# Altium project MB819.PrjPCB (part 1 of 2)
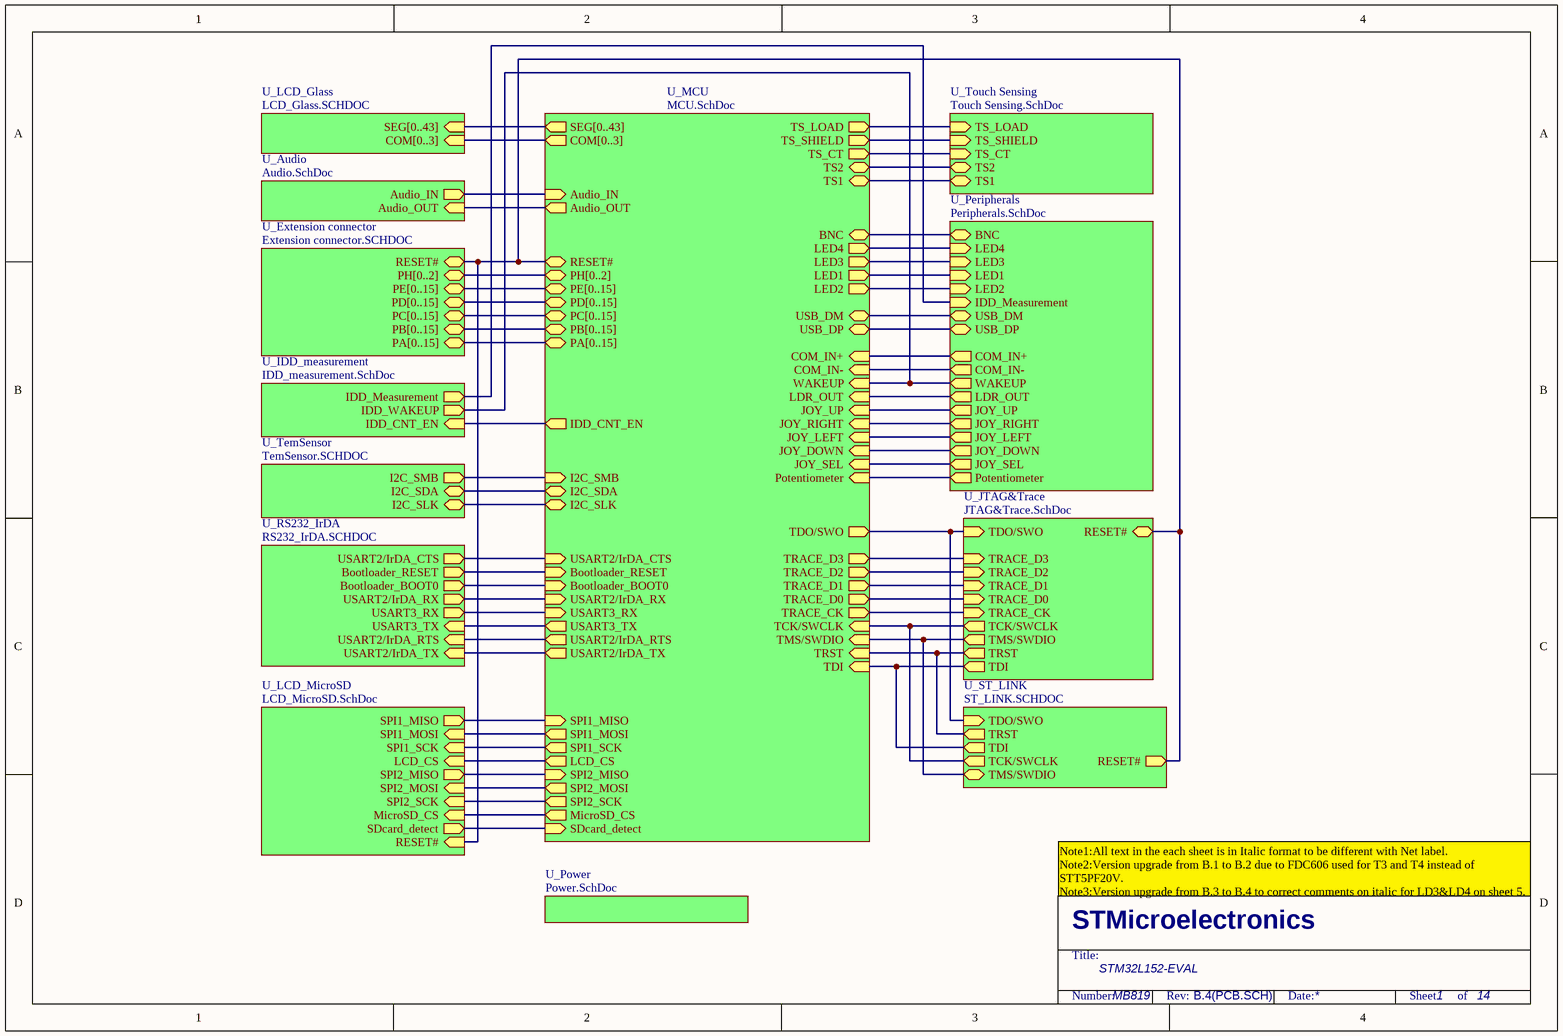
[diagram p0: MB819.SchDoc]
14 sheets, 334 parts. Net scope: hierarchical (ports join the sheet entries above them; power ports are global).
Board file: MB819.PCBDOC
Sheets:
  MB819.SchDoc
    U_Audio = Audio.SchDoc
    U_Extension connector = Extension connector.SCHDOC
    U_JTAG&Trace = JTAG&Trace.SchDoc
    U_LCD_Glass = LCD_Glass.SCHDOC
    U_LCD_MicroSD = LCD_MicroSD.SchDoc
    U_MCU = MCU.SchDoc
    U_Peripherals = Peripherals.SchDoc
    U_Power = Power.SchDoc
    U_RS232_IrDA = RS232_IrDA.SCHDOC
    U_ST_LINK = ST_LINK.SCHDOC
    U_TemSensor = TemSensor.SCHDOC
    U_Touch Sensing = Touch Sensing.SchDoc
    U_IDD_measurement = IDD_measurement.SchDoc

## Sheet MB819.SchDoc
size A4; Revision: B.4(PCB.SCH)

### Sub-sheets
U_Audio = Audio.SchDoc: Audio_OUT (in), Audio_IN (out)
U_Extension connector = Extension connector.SCHDOC: PA[0..15] (bidir), PB[0..15] (bidir), PC[0..15] (bidir), PD[0..15] (bidir), PE[0..15] (bidir), RESET# (bidir), PH[0..2] (bidir)
U_IDD_measurement = IDD_measurement.SchDoc: IDD_Measurement (out), IDD_CNT_EN (in), IDD_WAKEUP (out)
U_JTAG&Trace = JTAG&Trace.SchDoc: TDI (out), TRST (out), TMS/SWDIO (out), TCK/SWCLK (out), TDO/SWO (in), TRACE_D3 (in), TRACE_D2 (in), TRACE_D1 (in), TRACE_D0 (in), TRACE_CK (in), RESET# (bidir)
U_LCD_Glass = LCD_Glass.SCHDOC: SEG[0..43] (in), COM[0..3] (in)
U_LCD_MicroSD = LCD_MicroSD.SchDoc: MicroSD_CS (in), SPI1_SCK (in), SPI1_MOSI (in), LCD_CS (in), SPI1_MISO (out), SDcard_detect (out), RESET# (in), SPI2_SCK (in), SPI2_MOSI (in), SPI2_MISO (out)
U_MCU = MCU.SchDoc: PA[0..15] (bidir), PB[0..15] (bidir), PC[0..15] (bidir), PD[0..15] (bidir), PE[0..15] (bidir), RESET# (bidir), Bootloader_BOOT0 (in), Bootloader_RESET (in), PH[0..2] (bidir), TRACE_D3 (out), TRACE_D2 (out), TRACE_D1 (out), TRACE_D0 (out), TRACE_CK (out), SEG[0..43] (out), WAKEUP (in), Audio_OUT (out), BNC (bidir), TS_LOAD (out), SDcard_detect (in), JOY_SEL (in), JOY_DOWN (in), JOY_LEFT (in), JOY_RIGHT (in), JOY_UP (in), MicroSD_CS (out), SPI1_SCK (out), SPI1_MOSI (out), LCD_CS (out), SPI1_MISO (in), SPI2_SCK (out), SPI2_MOSI (out), SPI2_MISO (in), Potentiometer (in), Audio_IN (in), IDD_CNT_EN (out), TS1 (bidir), TS2 (bidir), TS_SHIELD (out), TS_CT (out), COM[0..3] (out), USB_DM (bidir), USB_DP (bidir), TDI (in), TRST (in), TMS/SWDIO (in), TCK/SWCLK (in), TDO/SWO (out), USART3_TX (out), USART3_RX (in), LED4 (out), LED3 (out), LED1 (out), LED2 (out), USART2/IrDA_TX (out), USART2/IrDA_CTS (in), USART2/IrDA_RX (in), USART2/IrDA_RTS (out), LDR_OUT (in), COM_IN- (in), COM_IN+ (in), I2C_SLK (bidir), I2C_SDA (bidir), I2C_SMB (in)
U_Peripherals = Peripherals.SchDoc: BNC (bidir), Potentiometer (out), LED4 (in), LED3 (in), LED1 (in), LED2 (in), JOY_SEL (out), JOY_DOWN (out), JOY_LEFT (out), JOY_RIGHT (out), JOY_UP (out), LDR_OUT (out), USB_DM (bidir), USB_DP (bidir), WAKEUP (out), COM_IN- (out), COM_IN+ (out), IDD_Measurement (in)
U_Power = Power.SchDoc: no entries
U_RS232_IrDA = RS232_IrDA.SCHDOC: USART2/IrDA_TX (in), USART2/IrDA_CTS (out), Bootloader_RESET (out), Bootloader_BOOT0 (out), USART2/IrDA_RX (out), USART2/IrDA_RTS (in), USART3_TX (in), USART3_RX (out)
U_ST_LINK = ST_LINK.SCHDOC: TMS/SWDIO (bidir), TCK/SWCLK (out), TDO/SWO (in), TDI (out), TRST (out), RESET# (out)
U_TemSensor = TemSensor.SCHDOC: I2C_SLK (bidir), I2C_SDA (bidir), I2C_SMB (out)
U_Touch Sensing = Touch Sensing.SchDoc: TS_LOAD (in), TS1 (bidir), TS2 (bidir), TS_SHIELD (in), TS_CT (in)

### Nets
PC8: sheet U_MCU/TS_SHIELD, sheet U_Touch Sensing/TS_SHIELD
PA0: sheet U_MCU/WAKEUP, sheet U_Peripherals/WAKEUP, sheet U_IDD_measurement/IDD_WAKEUP
PA4: sheet U_Audio/Audio_OUT, sheet U_MCU/Audio_OUT
PA5: sheet U_MCU/BNC, sheet U_Peripherals/BNC
PA11: sheet U_MCU/USB_DM, sheet U_Peripherals/USB_DM
PA12: sheet U_MCU/USB_DP, sheet U_Peripherals/USB_DP
PA13: sheet U_JTAG&Trace/TMS/SWDIO, sheet U_MCU/TMS/SWDIO, sheet U_ST_LINK/TMS/SWDIO
PA14: sheet U_JTAG&Trace/TCK/SWCLK, sheet U_MCU/TCK/SWCLK, sheet U_ST_LINK/TCK/SWCLK
PA15: sheet U_JTAG&Trace/TDI, sheet U_MCU/TDI, sheet U_ST_LINK/TDI
PB2: sheet U_MCU/TS_LOAD, sheet U_Touch Sensing/TS_LOAD
PB3: sheet U_JTAG&Trace/TDO/SWO, sheet U_MCU/TDO/SWO, sheet U_MCU/COM_IN-, sheet U_Peripherals/COM_IN-, sheet U_ST_LINK/TDO/SWO
PB5: sheet U_MCU/COM_IN+, sheet U_Peripherals/COM_IN+
PB6: sheet U_MCU/I2C_SLK, sheet U_TemSensor/I2C_SLK
PB7: sheet U_MCU/I2C_SDA, sheet U_TemSensor/I2C_SDA
PB12: sheet U_MCU/Potentiometer, sheet U_Peripherals/Potentiometer
PB13: sheet U_LCD_MicroSD/SPI2_SCK, sheet U_MCU/SPI2_SCK
PB14: sheet U_LCD_MicroSD/SPI2_MISO, sheet U_MCU/SPI2_MISO
PB15: sheet U_LCD_MicroSD/SPI2_MOSI, sheet U_MCU/SPI2_MOSI
PC6: sheet U_MCU/TS1, sheet U_Touch Sensing/TS1
PC7: sheet U_MCU/TS2, sheet U_Touch Sensing/TS2
PC9: sheet U_MCU/TS_CT, sheet U_Touch Sensing/TS_CT
PC13: sheet U_MCU/IDD_CNT_EN, sheet U_IDD_measurement/IDD_CNT_EN
PD0: sheet U_MCU/LED1, sheet U_Peripherals/LED1
PD1: sheet U_MCU/LED2, sheet U_Peripherals/LED2
PD3: sheet U_MCU/USART2/IrDA_CTS, sheet U_RS232_IrDA/USART2/IrDA_CTS
PD4: sheet U_MCU/USART2/IrDA_RTS, sheet U_RS232_IrDA/USART2/IrDA_RTS
PD5: sheet U_MCU/USART2/IrDA_TX, sheet U_RS232_IrDA/USART2/IrDA_TX
PD6: sheet U_MCU/USART2/IrDA_RX, sheet U_RS232_IrDA/USART2/IrDA_RX
PD7: sheet U_LCD_MicroSD/MicroSD_CS, sheet U_MCU/MicroSD_CS
PE2: sheet U_JTAG&Trace/TRACE_CK, sheet U_MCU/TRACE_CK
PE3: sheet U_JTAG&Trace/TRACE_D0, sheet U_MCU/TRACE_D0
PE4: sheet U_JTAG&Trace/TRACE_D1, sheet U_MCU/TRACE_D1
PE5: sheet U_JTAG&Trace/TRACE_D2, sheet U_MCU/TRACE_D2
PE6: sheet U_JTAG&Trace/TRACE_D3, sheet U_MCU/TRACE_D3
PE7: sheet U_Audio/Audio_IN, sheet U_MCU/Audio_IN
PE8: sheet U_MCU/JOY_SEL, sheet U_Peripherals/JOY_SEL
PE9: sheet U_MCU/JOY_UP, sheet U_Peripherals/JOY_UP
PE10: sheet U_MCU/JOY_DOWN, sheet U_Peripherals/JOY_DOWN
PE11: sheet U_MCU/JOY_RIGHT, sheet U_Peripherals/JOY_RIGHT
PE12: sheet U_MCU/JOY_LEFT, sheet U_Peripherals/JOY_LEFT
PE13: sheet U_LCD_MicroSD/SPI1_SCK, sheet U_MCU/SPI1_SCK
PE14: sheet U_LCD_MicroSD/SPI1_MISO, sheet U_MCU/SPI1_MISO
PE15: sheet U_LCD_MicroSD/SPI1_MOSI, sheet U_MCU/SPI1_MOSI
PH2: sheet U_LCD_MicroSD/LCD_CS, sheet U_MCU/LCD_CS
RESET#: sheet U_Extension connector/RESET#, sheet U_JTAG&Trace/RESET#, sheet U_LCD_MicroSD/RESET#, sheet U_MCU/RESET#, sheet U_ST_LINK/RESET#
T_JRST: sheet U_JTAG&Trace/TRST, sheet U_MCU/TRST, sheet U_ST_LINK/TRST
NetC25_1: sheet U_Peripherals/IDD_Measurement, sheet U_IDD_measurement/IDD_Measurement
NetCN4_10: sheet U_LCD_MicroSD/SDcard_detect, sheet U_MCU/SDcard_detect
NetD2_2: sheet U_MCU/Bootloader_RESET, sheet U_RS232_IrDA/Bootloader_RESET
NetJP7_3: sheet U_MCU/USART3_TX, sheet U_RS232_IrDA/USART3_TX
NetJP8_3: sheet U_MCU/USART3_RX, sheet U_RS232_IrDA/USART3_RX
NetJP10_1: sheet U_MCU/LDR_OUT, sheet U_Peripherals/LDR_OUT
NetJP11_2: sheet U_MCU/I2C_SMB, sheet U_TemSensor/I2C_SMB
NetJP18_1: sheet U_MCU/LED3, sheet U_Peripherals/LED3
NetJP19_1: sheet U_MCU/LED4, sheet U_Peripherals/LED4
NetR138_2: sheet U_MCU/Bootloader_BOOT0, sheet U_RS232_IrDA/Bootloader_BOOT0

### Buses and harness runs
bus sheet U_Extension connector/PA[0..15] = sheet U_MCU/PA[0..15]
bus sheet U_Extension connector/PB[0..15] = sheet U_MCU/PB[0..15]
bus sheet U_Extension connector/PC[0..15] = sheet U_MCU/PC[0..15]
bus sheet U_Extension connector/PD[0..15] = sheet U_MCU/PD[0..15]
bus sheet U_Extension connector/PE[0..15] = sheet U_MCU/PE[0..15]
bus sheet U_Extension connector/PH[0..2] = sheet U_MCU/PH[0..2]
bus sheet U_LCD_Glass/COM[0..3] = sheet U_MCU/COM[0..3]
bus sheet U_LCD_Glass/SEG[0..43] = sheet U_MCU/SEG[0..43]

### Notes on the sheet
- Note1:All text in the each sheet is in Italic format to be different with Net label.
  Note2:Version upgrade from B.1 to B.2 due to FDC606 used for T3 and T4 instead of STT5PF20V.
  Note3:Version upgrade from B.3 to B.4 to correct comments on italic for LD3&LD4 on sheet 5.
- STM32L152-EVAL
- MB819
- 1
- 14

## Sheet Audio.SchDoc
size A4; Revision: B.4(PCB.SCH)
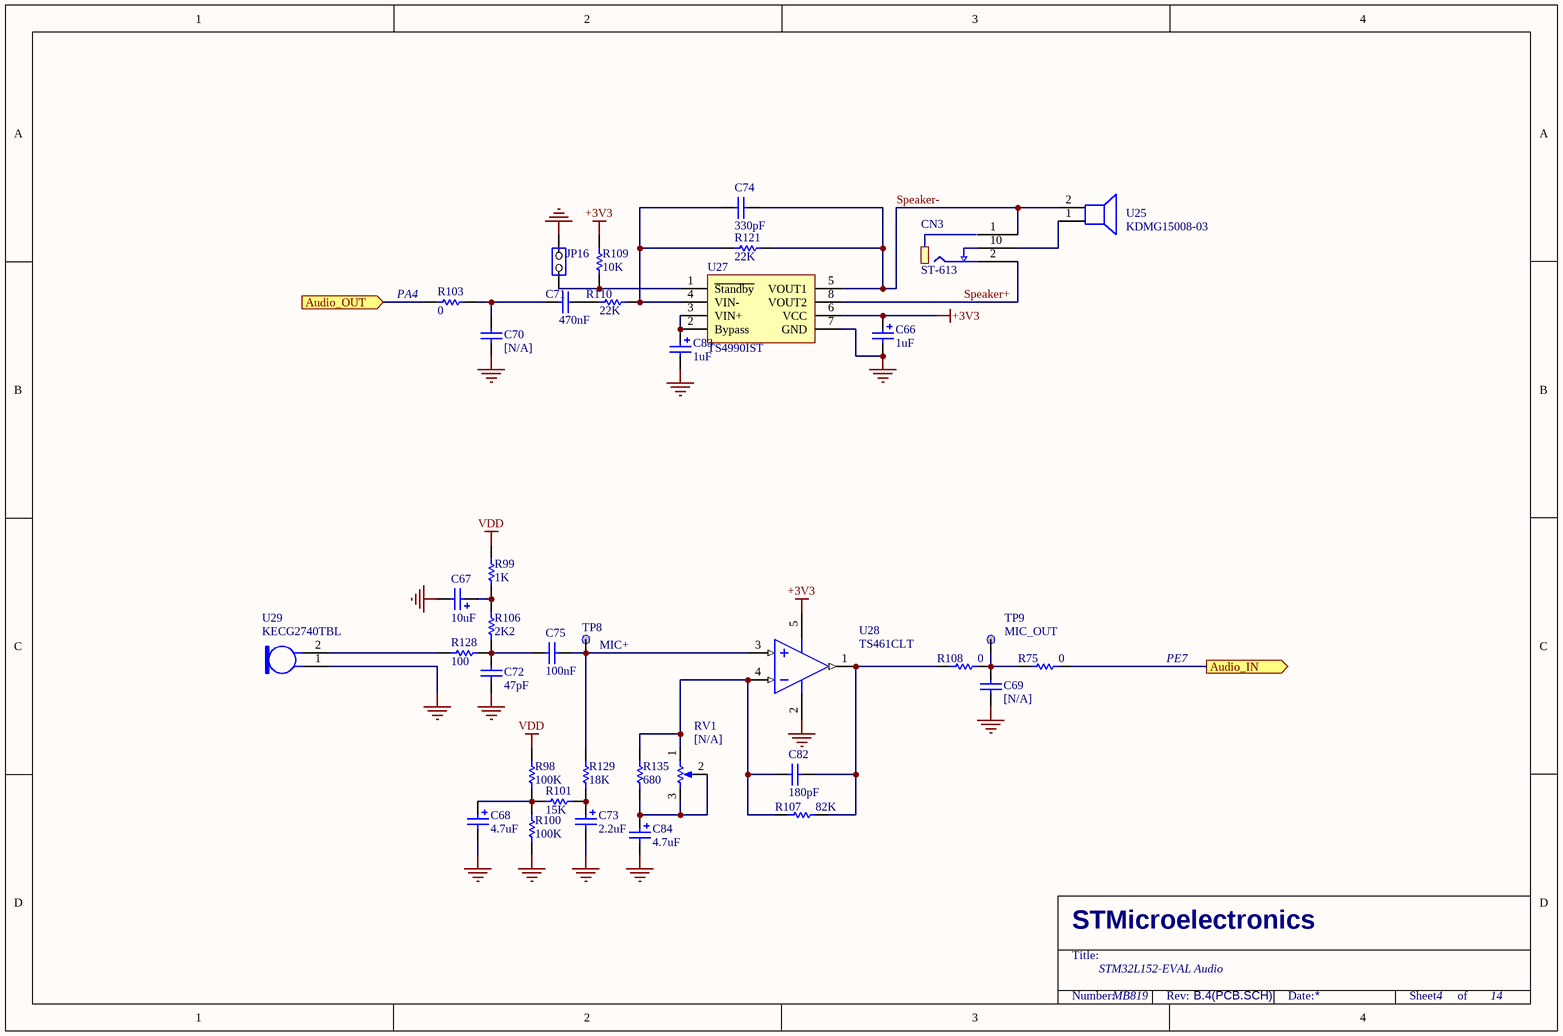
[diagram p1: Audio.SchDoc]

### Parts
C66  1uF  [0603C]
C67  10uF  [TAN-A]
C68  4.7uF  [TAN-A]
C69  [N/A]  [0603C]
C70  [N/A]  [0603C]
C71  470nF  [0603R]
C72  47pF  [0603C]
C73  2.2uF  [0805C]
C74  330pF  [0603C]
C75  100nF  [0402C]
C82  180pF  [0603C]
C83  1uF  [0603C]
C84  4.7uF  [TAN-A]
CN3  ST-613  [PJST-613]
JP16  (no value)  [SIP2]
R75  0  [0603R]
R98  100K  [0603R]
R99  1K  [0402R]
R100  100K  [0603R]
R101  15K  [0603R]
R103  0  [0603R]
R106  2K2  [0603R]
R107  82K  [0603R]
R108  0  [0603R]
R109  10K  [0402R]
R110  22K  [0603R]
R121  22K  [0603R]
R128  100  [0603R]
R129  18K  [0603R]
R135  680  [0402R]
RV1  [N/A]  [3314-J]
TP8  MIC+  [TP]
TP9  MIC_OUT  [TP]
U25  KDMG15008-03  [KS1508]
U27  TS4990IST  [MSOP8]
U28  TS461CLT  [SOT-23-5L]
U29  KECG2740TBL  [KEC2740]

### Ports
Audio_IN (out), Audio_OUT (in)

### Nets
+3V3: C66.1 R109.2 U27.6(VCC) U28.5(VCC)
GND: C66.2 C67.2 C68.2 C69.2 C70.1 C72.2 C73.2 C83.2 C84.2 JP16.2(NO) R100.2 U27.7(GND) U28.2(VDD) U29.1
VDD: R98.1 R99.2
PA4: R103.1 ; port Audio_OUT
PE7: R75.1 ; port Audio_IN
Speaker+: CN3.2 U27.8(VOUT2)
Speaker-: C74.2 CN3.1 R121.2 U25.2(--) U27.5(VOUT1)
NetC67_1: C67.1 R99.1 R106.2
NetC68_1: C68.1 R98.2 R100.1 R101.1
NetC69_1: C69.1 R75.2 R108.1 TP9.1
NetC70_2: C70.2 C71.1 R103.2
NetC71_2: C71.2 R110.1
NetC72_1: C72.1 C75.1 R106.1 R128.1
NetC73_1: C73.1 R101.2 R129.1
NetC74_1: C74.1 R110.2 R121.1 U27.4(VIN-)
NetC75_2: C75.2 R129.2 TP8.1 U28.3(IN+)
NetC82_1: C82.1 R107.2 R135.1 RV1.1(BOT) U28.4(IN-)
NetC82_2: C82.2 R107.1 R108.2 U28.1(OUT)
NetC83_1: C83.1 U27.2(Bypass) U27.3(VIN+)
NetC84_1: C84.1 R135.2 RV1.2(TAP) RV1.3(TOP)
NetCN3_10: CN3.10 U25.1(+)
NetJP16_1: JP16.1(COMMON) R109.1 U27.1(~{Standby})
NetR128_2: R128.2 U29.2

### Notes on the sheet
- (near R103) PA4
- PE7
- STM32L152-EVAL Audio
- MB819
- 4
- 14

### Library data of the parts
C66-C68 C73 C83 C84 = Cap Pol1: Polarized Capacitor (Radial); Value: 100pF
C69 = CAP: Capacitor; Value: 100nF
C70-C72 C74 C75 C82 = CAP: Capacitor; Value: 100pF
JP16 = JP2
R75 R98 R100 R101 R103 R106-R110 R121 R128 R129 R135 = Res1: Resistor; Value: 1K
R99 = Res1: Resistor
RV1 = RV
TP8 TP9 = TP
U25 = Speaker: Loudspeaker
U27 = ST4990IST
U29 = Mic2: Microphone

## Sheet Extension connector.SCHDOC
size A4; Revision: B.4(PCB.SCH)
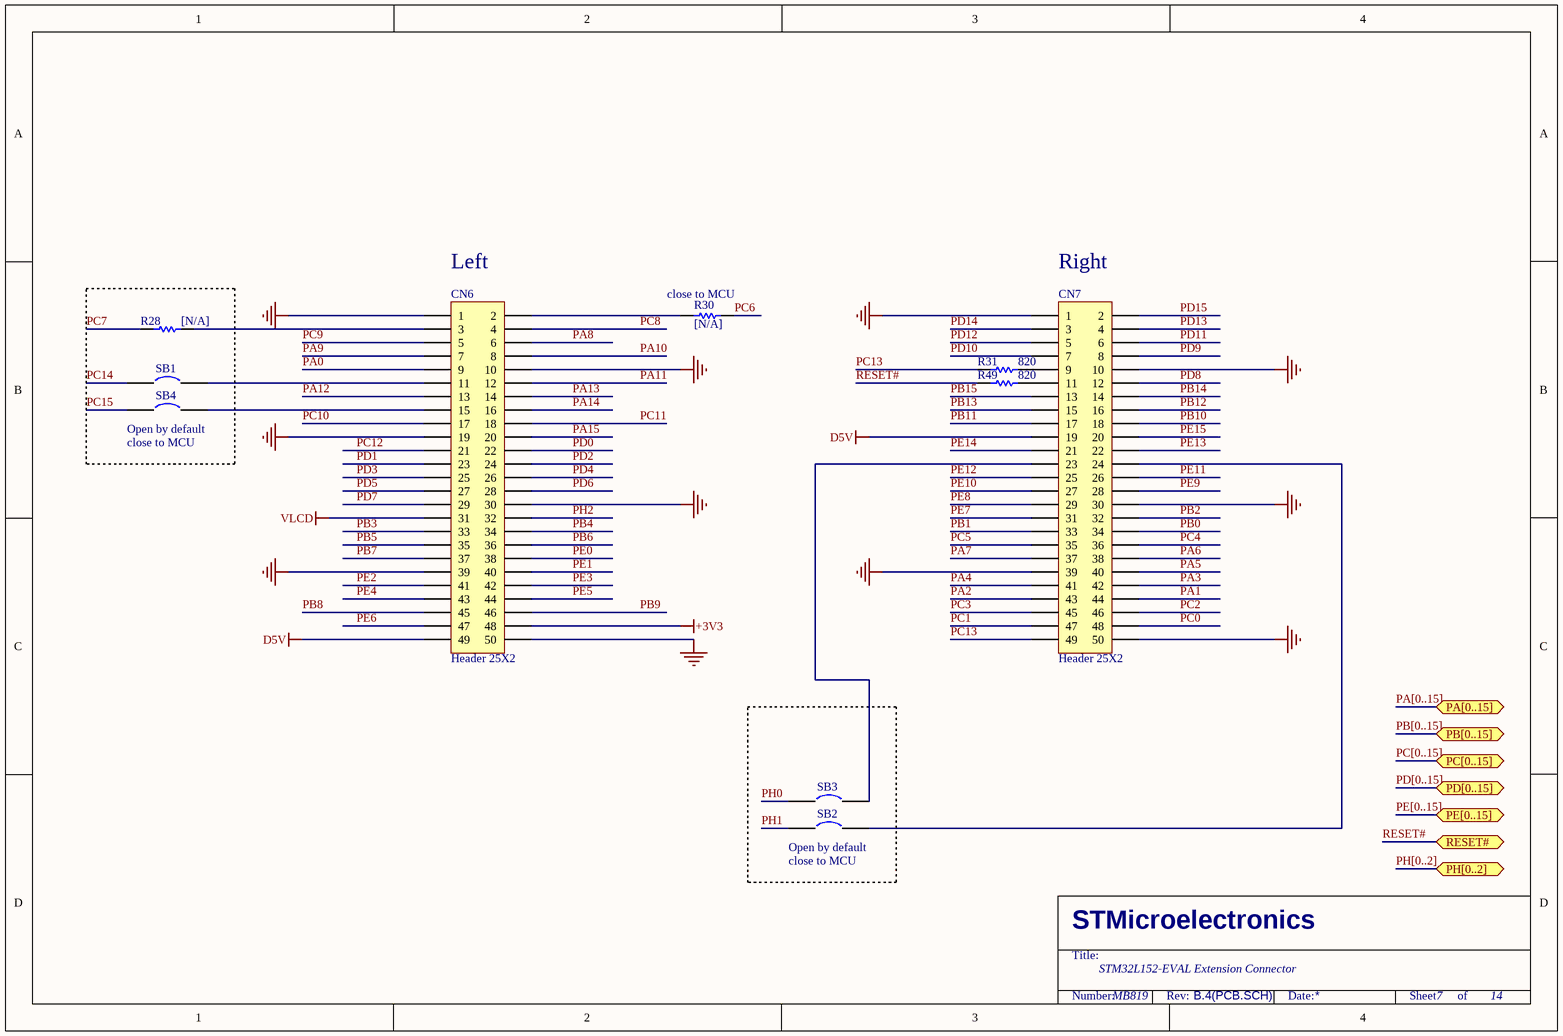
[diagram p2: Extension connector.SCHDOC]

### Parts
CN6  Header 25X2  [2*25P]
CN7  Header 25X2  [2*25P]
R28  [N/A]  [0603R]
R30  [N/A]  [0603R]
R31  820  [0603R]
R49  820  [0603R]
SB1  (no value)  [JP2_SMD]
SB2  (no value)  [JP2_SMD]
SB3  (no value)  [JP2_SMD]
SB4  (no value)  [JP2_SMD]

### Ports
PA[0..15] (bidir), PB[0..15] (bidir), PC[0..15] (bidir), PD[0..15] (bidir), PE[0..15] (bidir), PH[0..2] (bidir), RESET# (bidir)

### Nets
+3V3: CN6.48
D5V: CN6.49 CN7.19
GND: CN6.1 CN6.10 CN6.19 CN6.30 CN6.39 CN6.50 CN7.1 CN7.10 CN7.30 CN7.39 CN7.50
PC8: CN6.4
VLCD: CN6.31
PA0: CN6.9
PA1: CN7.44
PA2: CN7.43
PA3: CN7.42
PA4: CN7.41
PA5: CN7.40
PA6: CN7.38
PA7: CN7.37
PA8: CN6.6  [project net COM0]
PA9: CN6.7  [project net COM1]
PA10: CN6.8  [project net COM2]
PA11: CN6.12
PA12: CN6.13
PA13: CN6.14
PA14: CN6.16
PA15: CN6.20
PB0: CN7.34
PB1: CN7.33
PB2: CN7.32
PB3: CN6.33
PB4: CN6.34
PB5: CN6.35
PB6: CN6.36
PB7: CN6.37
PB8: CN6.45
PB9: CN6.46  [project net COM3]
PB10: CN7.18
PB11: CN7.17
PB12: CN7.16
PB13: CN7.15
PB14: CN7.14
PB15: CN7.13
PC0: CN7.48
PC1: CN7.47
PC2: CN7.46
PC3: CN7.45
PC4: CN7.36
PC5: CN7.35
PC6: R30.1
PC7: R28.2
PC9: CN6.5
PC10: CN6.17
PC11: CN6.18
PC12: CN6.21
PC13: CN7.49 R31.1
PC14: SB1.1
PC15: SB4.1
PD0: CN6.22
PD1: CN6.23
PD2: CN6.24
PD3: CN6.25
PD4: CN6.26
PD5: CN6.27
PD6: CN6.28
PD7: CN6.29
PD8: CN7.12
PD9: CN7.8
PD10: CN7.7
PD11: CN7.6
PD12: CN7.5
PD13: CN7.4
PD14: CN7.3
PD15: CN7.2
PE0: CN6.38
PE1: CN6.40
PE2: CN6.41
PE3: CN6.42
PE4: CN6.43
PE5: CN6.44
PE6: CN6.47
PE7: CN7.31
PE8: CN7.29
PE9: CN7.28
PE10: CN7.27
PE11: CN7.26
PE12: CN7.25
PE13: CN7.22
PE14: CN7.21
PE15: CN7.20
PH0: SB3.1
PH1: SB2.1
PH2: CN6.32
RESET#: R49.2 ; port RESET#
NetCN6_2: CN6.2 R30.2
NetCN6_3: CN6.3 R28.1
NetCN6_11: CN6.11 SB1.2
NetCN6_15: CN6.15 SB4.2
NetCN7_9: CN7.9 R31.2
NetCN7_11: CN7.11 R49.1
NetCN7_23: CN7.23 SB3.2
NetCN7_24: CN7.24 SB2.2

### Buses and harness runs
bus PA[0..15] = port PA[0..15]
bus PB[0..15] = port PB[0..15]
bus PC[0..15] = port PC[0..15]
bus PD[0..15] = port PD[0..15]
bus PE[0..15] = port PE[0..15]
bus PH[0..2] = port PH[0..2]

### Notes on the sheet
- (near CN6) Left
- (near R30) close to MCU
- (near CN7) Right
- (near SB4) close to MCU
- (near SB4) Open by default
- (near SB2) Open by default
- (near SB2) close to MCU
- STM32L152-EVAL Extension Connector
- MB819
- 7
- 14

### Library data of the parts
CN6 CN7 = Header 25X2: Header, 25-Pin, Dual row
R28 R30 R31 R49 = Res1: Resistor; Value: 1K
SB1-SB4 = Circuit Breaker

## Sheet JTAG&Trace.SchDoc
size A4; Revision: B.4(PCB.SCH)
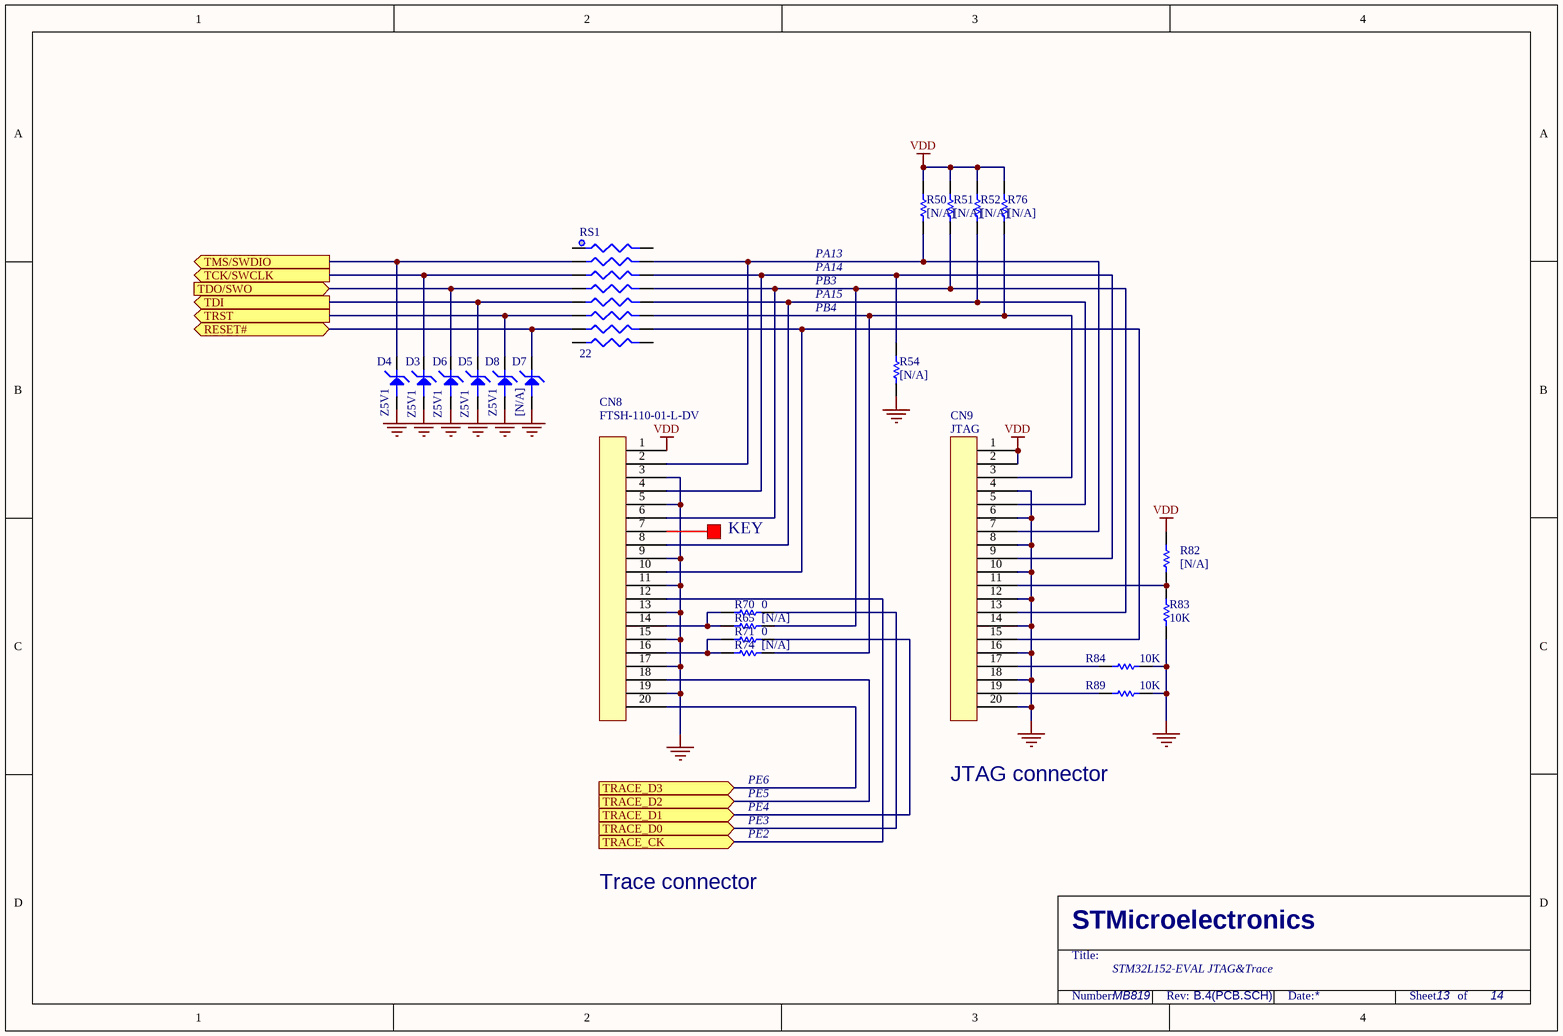
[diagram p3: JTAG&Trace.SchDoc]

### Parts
CN8  FTSH-110-01-L-DV  [FTSH-110-01-L-DV]
CN9  JTAG  [IDC20S]
D3  Z5V1  [SOT-23]
D4  Z5V1  [SOT-23]
D5  Z5V1  [SOT-23]
D6  Z5V1  [SOT-23]
D7  [N/A]  [SOT-23]
D8  Z5V1  [SOT-23]
R50  [N/A]  [0402R]
R51  [N/A]  [0402R]
R52  [N/A]  [0402R]
R54  [N/A]  [0402R]
R65  [N/A]  [0603R]
R70  0  [0603R]
R71  0  [0603R]
R74  [N/A]  [0603R]
R76  [N/A]  [0402R]
R82  [N/A]  [0402R]
R83  10K  [0402R]
R84  10K  [0402R]
R89  10K  [0402R]
RS1  22  [RES8B_0402]

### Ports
RESET# (bidir), TCK/SWCLK (out), TDI (out), TDO/SWO (in), TMS/SWDIO (out), TRACE_CK (in), TRACE_D0 (in), TRACE_D1 (in), TRACE_D2 (in), TRACE_D3 (in), TRST (out)

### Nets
GND: CN8.3 CN8.5 CN8.9 CN8.11 CN8.13 CN8.15 CN8.17 CN8.19 CN9.4 CN9.6 CN9.8 CN9.10 CN9.12 CN9.14 CN9.16 CN9.18 CN9.20 D3.2 D4.2 D5.2 D6.2 D7.2 D8.2 R54.1 R83.1 R84.1 R89.1
VDD: CN8.1 CN9.1 CN9.2 R50.2 R51.2 R52.2 R76.2 R82.2
PA13: D4.3 RS1.3 ; port TMS/SWDIO
PA14: D3.3 RS1.5 ; port TCK/SWCLK
PA15: D5.3 RS1.9 ; port TDI
PB3: D6.3 RS1.7 ; port TDO/SWO
PE2: CN8.12 ; port TRACE_CK
PE3: R70.2 ; port TRACE_D0
PE4: R71.2 ; port TRACE_D1
PE5: CN8.18 ; port TRACE_D2
PE6: CN8.20 ; port TRACE_D3
RESET#: D7.3 RS1.13 ; port RESET#
T_JRST: D8.3 RS1.11 ; port TRST
NetCN8_2: CN8.2 CN9.7 R50.1 RS1.4
NetCN8_4: CN8.4 CN9.9 R54.2 RS1.6
NetCN8_6: CN8.6 CN9.13 R51.1 R65.2 RS1.8
NetCN8_8: CN8.8 CN9.5 R52.1 RS1.10
NetCN8_10: CN8.10 CN9.15 RS1.14
NetCN8_14: CN8.14 R65.1 R70.1
NetCN8_16: CN8.16 R71.1 R74.1
NetCN9_3: CN9.3 R74.2 R76.1 RS1.12
NetCN9_11: CN9.11 R82.1 R83.2
NetCN9_17: CN9.17 R84.2
NetCN9_19: CN9.19 R89.2

Not connected (* = marked no-connect by the designer): CN8 7; RS1 1 2 15 16

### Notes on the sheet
- PA13
- PA14
- PB3
- PA15
- PB4
- KEY
- PE6
- JTAG connector
- PE5
- PE4
- PE3
- PE2
- Trace connector
- STM32L152-EVAL JTAG&Trace
- MB819
- 13
- 14

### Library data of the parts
CN8 CN9 = 20PIN1
D3-D8 = Z5V6
R50-R52 R54 R65 R70 R71 R74 R76 R82-R84 R89 = Res1: Resistor; Value: 1K
RS1 = RES8B

## Sheet LCD_Glass.SCHDOC
size A4; Revision: B.4(PCB.SCH)
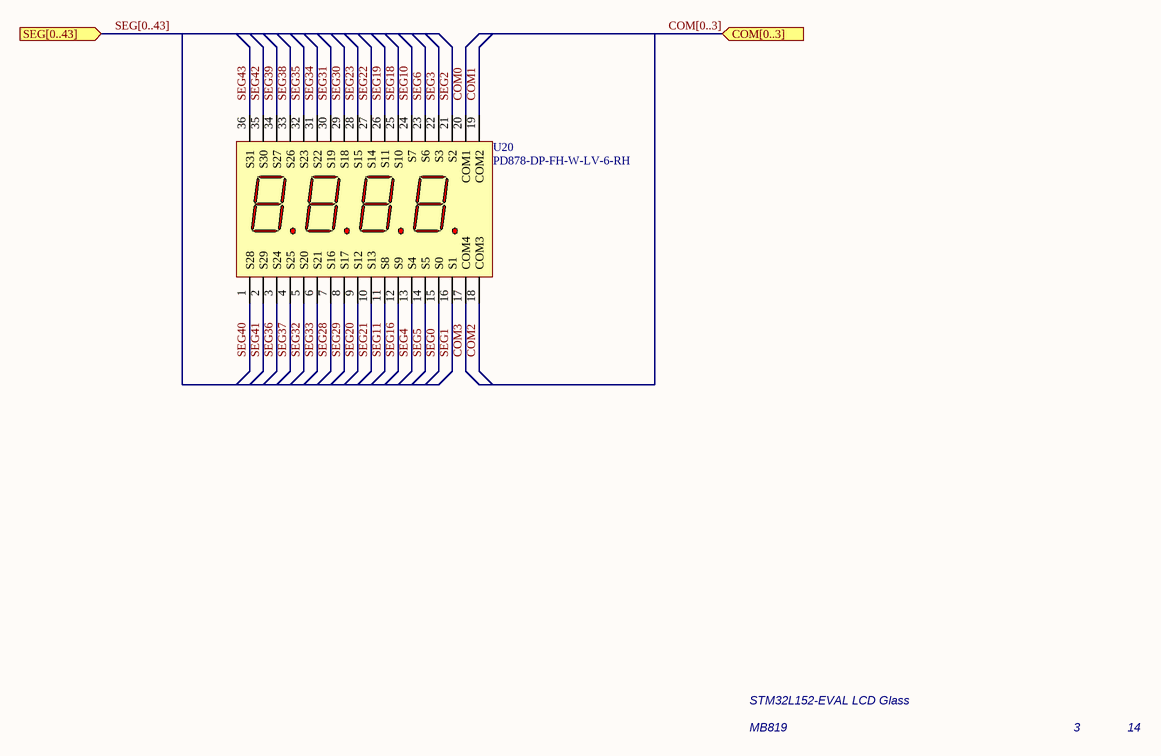
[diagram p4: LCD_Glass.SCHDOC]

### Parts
U20  PD878-DP-FH-W-LV-6-RH  [PD-878]

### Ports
COM[0..3] (in), SEG[0..43] (in)

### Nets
COM0: U20.20(COM1)
COM1: U20.19(COM2)
COM2: U20.18(COM3)
COM3: U20.17(COM4)
SEG0: U20.15(S0)  [project net PA1]
SEG1: U20.16(S1)  [project net PA2]
SEG2: U20.21(S2)  [project net PA3]
SEG3: U20.22(S3)  [project net PA6]
SEG4: U20.13(S4)  [project net PA7]
SEG5: U20.14(S5)  [project net PB0]
SEG6: U20.23(S6)  [project net PB1]
SEG10: U20.24(S7)  [project net PB10]
SEG11: U20.11(S8)  [project net PB11]
SEG16: U20.12(S9)  [project net PB8]
SEG18: U20.25(S10)  [project net PC0]
SEG19: U20.26(S11)  [project net PC1]
SEG20: U20.9(S12)  [project net PC2]
SEG21: U20.10(S13)  [project net PC3]
SEG22: U20.27(S14)  [project net PC4]
SEG23: U20.28(S15)  [project net PC5]
SEG28: U20.7(S16)  [project net PD8]
SEG29: U20.8(S17)  [project net PD9]
SEG30: U20.29(S18)  [project net PD10]
SEG31: U20.30(S19)  [project net PD11]
SEG32: U20.5(S20)  [project net PD12]
SEG33: U20.6(S21)  [project net PD13]
SEG34: U20.31(S22)  [project net PD14]
SEG35: U20.32(S23)  [project net PD15]
SEG36: U20.3(S24)  [project net PE0]
SEG37: U20.4(S25)  [project net PE1]
SEG38: U20.33(S26)
SEG39: U20.34(S27)
SEG40: U20.1(S28)
SEG41: U20.2(S29)
SEG42: U20.35(S30)  [project net PC12]
SEG43: U20.36(S31)  [project net PD2]

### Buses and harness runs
bus COM[0..3] = port COM[0..3]
bus SEG[0..43] = port SEG[0..43]

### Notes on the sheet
- STM32L152-EVAL LCD Glass
- MB819
- 3
- 14

## Sheet LCD_MicroSD.SchDoc
size A4; Revision: B.4(PCB.SCH)
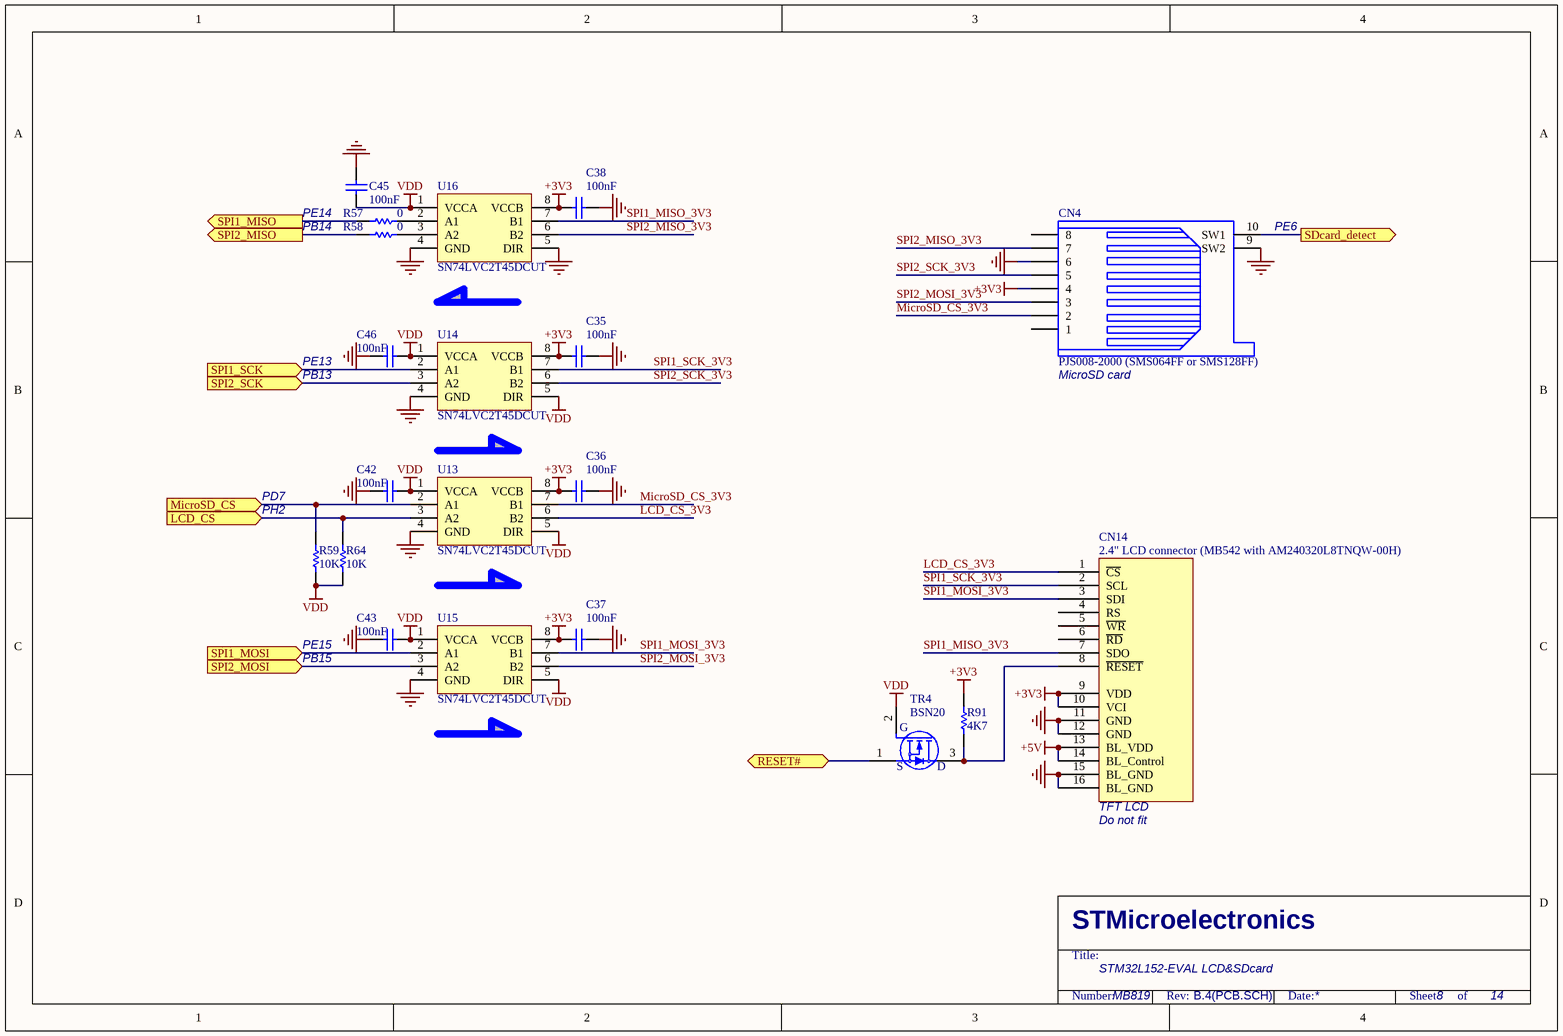
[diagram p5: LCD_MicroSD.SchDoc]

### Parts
C35  100nF  [0402C]
C36  100nF  [0402C]
C37  100nF  [0402C]
C38  100nF  [0402C]
C42  100nF  [0402C]
C43  100nF  [0402C]
C45  100nF  [0402C]
C46  100nF  [0402C]
CN4  PJS008-2000 (SMS064FF or SMS128FF)  [MSD(PJS008)]
CN14  2.4" LCD connector (MB542 with AM240320L8TNQW-00H)  [MB542]
R57  0  [0603R]
R58  0  [0603R]
R59  10K  [0402R]
R64  10K  [0402R]
R91  4K7  [0402R]
TR4  BSN20  [SOT-23]
U13  SN74LVC2T45DCUT  [VSSOP8]
U14  SN74LVC2T45DCUT  [VSSOP8]
U15  SN74LVC2T45DCUT  [VSSOP8]
U16  SN74LVC2T45DCUT  [VSSOP8]

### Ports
LCD_CS (in), MicroSD_CS (in), RESET# (bidir), SDcard_detect (out), SPI1_MISO (out), SPI1_MOSI (in), SPI1_SCK (in), SPI2_MISO (out), SPI2_MOSI (in), SPI2_SCK (in)

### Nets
+3V3: C35.2 C36.2 C37.2 C38.2 CN4.4 CN14.9(VDD) CN14.10(VCI) R91.2 U13.8(VCCB) U14.8(VCCB) U15.8(VCCB) U16.8(VCCB)
+5V: CN14.13(BL_VDD) CN14.14(BL_Control)
GND: C35.1 C36.1 C37.1 C38.1 C42.1 C43.1 C45.2 C46.1 CN4.6 CN4.9(SW2) CN14.11(GND) CN14.12(GND) CN14.15(BL_GND) CN14.16(BL_GND) U13.4(GND) U14.4(GND) U15.4(GND) U16.4(GND) U16.5(DIR)
VDD: C42.2 C43.2 C45.1 C46.2 R59.1 R64.1 TR4.2(G) U13.1(VCCA) U13.5(DIR) U14.1(VCCA) U14.5(DIR) U15.1(VCCA) U15.5(DIR) U16.1(VCCA)
LCD_CS_3V3: CN14.1(~{CS}) U13.6(B2)
MicroSD_CS_3V3: CN4.2 U13.7(B1)
PB13: U14.3(A2) ; port SPI2_SCK
PB14: R58.1 ; port SPI2_MISO
PB15: U15.3(A2) ; port SPI2_MOSI
PD7: R59.2 U13.2(A1) ; port MicroSD_CS
PE13: U14.2(A1) ; port SPI1_SCK
PE14: R57.1 ; port SPI1_MISO
PE15: U15.2(A1) ; port SPI1_MOSI
PH2: R64.2 U13.3(A2) ; port LCD_CS
RESET#: TR4.1(S) ; port RESET#
SPI1_MISO_3V3: CN14.7(SDO) U16.7(B1)
SPI1_MOSI_3V3: CN14.3(SDI) U15.7(B1)
SPI1_SCK_3V3: CN14.2(SCL) U14.7(B1)
SPI2_MISO_3V3: CN4.7 U16.6(B2)
SPI2_MOSI_3V3: CN4.3 U15.6(B2)
SPI2_SCK_3V3: CN4.5 U14.6(B2)
NetCN4_10: CN4.10(SW1) ; port SDcard_detect
NetCN14_8: CN14.8(~{RESET}) R91.1 TR4.3(D)
NetR57_2: R57.2 U16.2(A1)
NetR58_2: R58.2 U16.3(A2)

Not connected (* = marked no-connect by the designer): CN4 1 8; CN14 4(RS) 5(~{WR}) 6(~{RD})

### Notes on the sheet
- PE14
- PB14
- (near CN4) PE6
- PE13
- PB13
- (near CN4) MicroSD card
- PD7
- PH2
- PE15
- PB15
- (near CN14) Do not fit
- (near CN14) TFT LCD
- STM32L152-EVAL LCD&SDcard
- MB819
- 8
- 14

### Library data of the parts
C35-C38 C42 C43 C45 C46 = CAP: Capacitor; Value: 100pF
CN4 = SMS016AFA5E
CN14 = ColorLCD_module
R57-R59 R64 R91 = Res1: Resistor; Value: 1K
TR4 = 2N7000

## Sheet MCU.SchDoc
size A4; Revision: B.4(PCB.SCH)
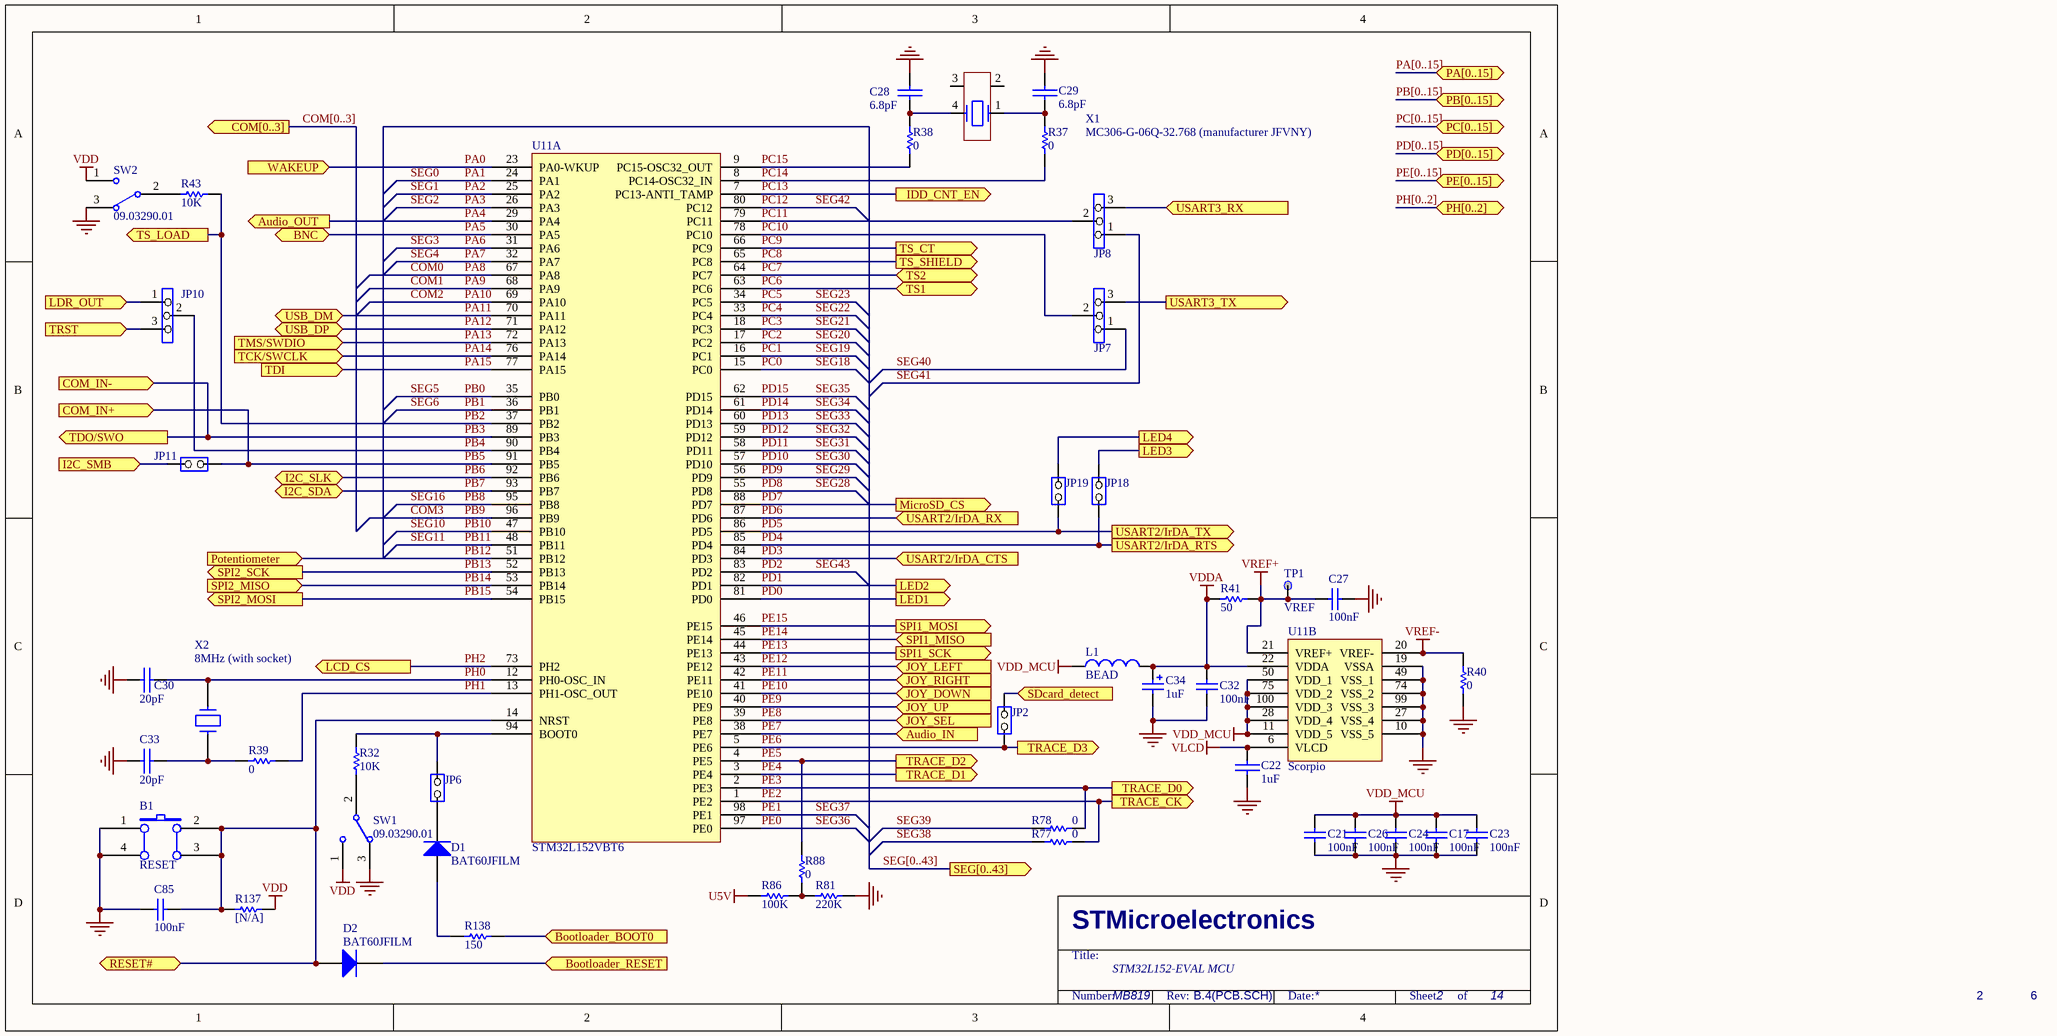
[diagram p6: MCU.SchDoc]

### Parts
B1  RESET  [PB10]
C17  100nF  [0402C]
C21  100nF  [0402C]
C22  1uF  [0603C]
C23  100nF  [0402C]
C24  100nF  [0402C]
C26  100nF  [0402C]
C27  100nF  [0402C]
C28  6.8pF  [0603C]
C29  6.8pF  [0603C]
C30  20pF  [0603C]
C32  100nF  [0402C]
C33  20pF  [0603C]
C34  1uF  [TAN-A]
C85  100nF  [0402C]
D1  BAT60JFILM  [SOD-323]
D2  BAT60JFILM  [SOD-323]
JP2  (no value)  [SIP2]
JP6  (no value)  [SIP2]
JP7  (no value)  [SIP3]
JP8  (no value)  [SIP3]
JP10  (no value)  [SIP3]
JP11  (no value)  [SIP2]
JP18  (no value)  [SIP2]
JP19  (no value)  [SIP2]
L1  BEAD  [0603C]
R32  10K  [0402R]
R37  0  [0603R]
R38  0  [0603R]
R39  0  [0603R]
R40  0  [0603R]
R41  50  [0603R]
R43  10K  [0402R]
R77  0  [0603R]
R78  0  [0603R]
R81  220K  [0603R]
R86  100K  [0603R]
R88  0  [0603R]
R137  [N/A]  [0603R]
R138  150  [0402R]
SW1  09.03290.01  [SIP3]
SW2  09.03290.01  [SIP3]
TP1  VREF  [TP]
U11  STM32L152VBT6  [TQ100_TOOL]  (parts A,B of 2)
X1  MC306-G-06Q-32.768 (manufacturer JFVNY)  [SM8]
X2  8MHz (with socket)  [XTAL_SOCKET]

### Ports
Audio_IN (in), Audio_OUT (out), BNC (bidir), Bootloader_BOOT0 (in), Bootloader_RESET (in), COM[0..3] (out), COM_IN+ (in), COM_IN- (in), I2C_SDA (bidir), I2C_SLK (bidir), I2C_SMB (in), IDD_CNT_EN (out), JOY_DOWN (in), JOY_LEFT (in), JOY_RIGHT (in), JOY_SEL (in), JOY_UP (in), LCD_CS (out), LDR_OUT (in), LED1 (out), LED2 (out), LED3 (out), LED4 (out), MicroSD_CS (out), PA[0..15] (bidir), PB[0..15] (bidir), PC[0..15] (bidir), PD[0..15] (bidir), PE[0..15] (bidir), PH[0..2] (bidir), Potentiometer (in), RESET# (bidir), SDcard_detect (in), SEG[0..43] (out), SPI1_MISO (in), SPI1_MOSI (out), SPI1_SCK (out), SPI2_MISO (in), SPI2_MOSI (out), SPI2_SCK (out), TCK/SWCLK (in), TDI (in), TDO/SWO (out), TMS/SWDIO (in), TRACE_CK (out), TRACE_D0 (out), TRACE_D1 (out), TRACE_D2 (out), TRACE_D3 (out), TRST (in), TS1 (bidir), TS2 (bidir), TS_CT (out), TS_LOAD (out), TS_SHIELD (out), USART2/IrDA_CTS (in), USART2/IrDA_RTS (out), USART2/IrDA_RX (in), USART2/IrDA_TX (out), USART3_RX (in), USART3_TX (out), USB_DM (bidir), USB_DP (bidir), WAKEUP (in)

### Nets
GND: B1.1(A0) B1.4(A1) C17.2 C21.2 C22.2 C23.2 C24.2 C26.2 C27.2 C28.2 C29.2 C30.2 C32.2 C33.2 C34.2 C85.1 R40.1 R81.2 SW1.3 SW2.3 U11.10(VSS_5) U11.19(VSSA) U11.27(VSS_4) U11.49(VSS_1) U11.74(VSS_2) U11.99(VSS_3)
PC8: U11.65(PC8) ; port TS_SHIELD
U5V: R86.1
VDD: R137.2 SW1.1 SW2.1
VDD_MCU: C17.1 C21.1 C23.1 C24.1 C26.1 L1.1 U11.11(VDD_5) U11.28(VDD_4) U11.50(VDD_1) U11.75(VDD_2) U11.100(VDD_3)
VDDA: C32.1 C34.1 L1.2 R41.2 U11.22(VDDA)
VLCD: C22.1 U11.6(VLCD)
VREF+: C27.1 R41.1 TP1.1 U11.21(VREF+)
VREF-: R40.2 U11.20(VREF-)
COM0: U11.67(PA8)  [also labelled PA8]
COM1: U11.68(PA9)  [also labelled PA9]
COM2: U11.69(PA10)  [also labelled PA10]
COM3: U11.96(PB9)  [also labelled PB9]
PA0: U11.23(PA0-WKUP) ; port WAKEUP
PA1: U11.24(PA1)  [also labelled SEG0]
PA2: U11.25(PA2)  [also labelled SEG1]
PA3: U11.26(PA3)  [also labelled SEG2]
PA4: U11.29(PA4) ; port Audio_OUT
PA5: U11.30(PA5) ; port BNC
PA6: U11.31(PA6)  [also labelled SEG3]
PA7: U11.32(PA7)  [also labelled SEG4]
PA11: U11.70(PA11) ; port USB_DM
PA12: U11.71(PA12) ; port USB_DP
PA13: U11.72(PA13) ; port TMS/SWDIO
PA14: U11.76(PA14) ; port TCK/SWCLK
PA15: U11.77(PA15) ; port TDI
PB0: U11.35(PB0)  [also labelled SEG5]
PB1: U11.36(PB1)  [also labelled SEG6]
PB2: R43.1 U11.37(PB2) ; port TS_LOAD
PB3: U11.89(PB3) ; port TDO/SWO, port COM_IN-
PB4: JP10.2 U11.90(PB4)
PB5: JP11.1(COMMON) U11.91(PB5) ; port COM_IN+
PB6: U11.92(PB6) ; port I2C_SLK
PB7: U11.93(PB7) ; port I2C_SDA
PB8: U11.95(PB8)  [also labelled SEG16]
PB10: U11.47(PB10)  [also labelled SEG10]
PB11: U11.48(PB11)  [also labelled SEG11]
PB12: U11.51(PB12) ; port Potentiometer
PB13: U11.52(PB13) ; port SPI2_SCK
PB14: U11.53(PB14) ; port SPI2_MISO
PB15: U11.54(PB15) ; port SPI2_MOSI
PC0: U11.15(PC0)  [also labelled SEG18]
PC1: U11.16(PC1)  [also labelled SEG19]
PC2: U11.17(PC2)  [also labelled SEG20]
PC3: U11.18(PC3)  [also labelled SEG21]
PC4: U11.33(PC4)  [also labelled SEG22]
PC5: U11.34(PC5)  [also labelled SEG23]
PC6: U11.63(PC6) ; port TS1
PC7: U11.64(PC7) ; port TS2
PC9: U11.66(PC9) ; port TS_CT
PC10: JP7.2 U11.78(PC10)
PC11: JP8.2 U11.79(PC11)
PC12: U11.80(PC12)  [also labelled SEG42]
PC13: U11.7(PC13-ANTI_TAMP) ; port IDD_CNT_EN
PC14: R37.2 U11.8(PC14-OSC32_IN)
PC15: R38.2 U11.9(PC15-OSC32_OUT)
PD0: U11.81(PD0) ; port LED1
PD1: U11.82(PD1) ; port LED2
PD2: U11.83(PD2)  [also labelled SEG43]
PD3: U11.84(PD3) ; port USART2/IrDA_CTS
PD4: JP18.2(NO) U11.85(PD4) ; port USART2/IrDA_RTS
PD5: JP19.2(NO) U11.86(PD5) ; port USART2/IrDA_TX
PD6: U11.87(PD6) ; port USART2/IrDA_RX
PD7: U11.88(PD7) ; port MicroSD_CS
PD8: U11.55(PD8)  [also labelled SEG28]
PD9: U11.56(PD9)  [also labelled SEG29]
PD10: U11.57(PD10)  [also labelled SEG30]
PD11: U11.58(PD11)  [also labelled SEG31]
PD12: U11.59(PD12)  [also labelled SEG32]
PD13: U11.60(PD13)  [also labelled SEG33]
PD14: U11.61(PD14)  [also labelled SEG34]
PD15: U11.62(PD15)  [also labelled SEG35]
PE0: U11.97(PE0)  [also labelled SEG36]
PE1: U11.98(PE1)  [also labelled SEG37]
PE2: R77.1 U11.1(PE2) ; port TRACE_CK
PE3: R78.1 U11.2(PE3) ; port TRACE_D0
PE4: U11.3(PE4) ; port TRACE_D1
PE5: R88.1 U11.4(PE5) ; port TRACE_D2
PE6: JP2.2(NO) U11.5(PE6) ; port TRACE_D3
PE7: U11.38(PE7) ; port Audio_IN
PE8: U11.39(PE8) ; port JOY_SEL
PE9: U11.40(PE9) ; port JOY_UP
PE10: U11.41(PE10) ; port JOY_DOWN
PE11: U11.42(PE11) ; port JOY_RIGHT
PE12: U11.43(PE12) ; port JOY_LEFT
PE13: U11.44(PE13) ; port SPI1_SCK
PE14: U11.45(PE14) ; port SPI1_MISO
PE15: U11.46(PE15) ; port SPI1_MOSI
PH0: C30.1 U11.12(PH0-OSC_IN) X2.2
PH1: R39.1 U11.13(PH1-OSC_OUT)
PH2: U11.73(PH2) ; port LCD_CS
RESET#: B1.2(B0) B1.3(B1) C85.2 D2.1(A) R137.1 U11.14(NRST) ; port RESET#
SEG38: R77.2
SEG39: R78.2
SEG40: JP7.1
SEG41: JP8.1
T_JRST: JP10.3 ; port TRST
NetC28_1: C28.1 R38.1 X1.4
NetC29_1: C29.1 R37.1 X1.1
NetC33_1: C33.1 R39.2 X2.1
NetCN4_10: JP2.1(COMMON) ; port SDcard_detect
NetD1_1: D1.1(A) R138.1
NetD1_2: D1.2(K) JP6.2(NO)
NetD2_2: D2.2(K) ; port Bootloader_RESET
NetJP6_1: JP6.1(COMMON) R32.1 U11.94(BOOT0)
NetJP7_3: JP7.3 ; port USART3_TX
NetJP8_3: JP8.3 ; port USART3_RX
NetJP10_1: JP10.1 ; port LDR_OUT
NetJP11_2: JP11.2(NO) ; port I2C_SMB
NetJP18_1: JP18.1(COMMON) ; port LED3
NetJP19_1: JP19.1(COMMON) ; port LED4
NetR32_2: R32.2 SW1.2
NetR43_2: R43.2 SW2.2
NetR81_1: R81.1 R86.2 R88.2
NetR138_2: R138.2 ; port Bootloader_BOOT0

Not connected (* = marked no-connect by the designer): X1 2 3

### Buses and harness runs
bus COM[0..3] = port COM[0..3]
bus PA[0..15] = port PA[0..15]
bus PB[0..15] = port PB[0..15]
bus PC[0..15] = port PC[0..15]
bus PD[0..15] = port PD[0..15]
bus PE[0..15] = port PE[0..15]
bus PH[0..2] = port PH[0..2]
bus SEG[0..43] = port SEG[0..43]

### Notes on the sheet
- STM32L152-EVAL MCU
- MB819
- 2
- 14
- 6

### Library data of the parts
B1 = SW PUSHBUTTON: SE PUSHBUTTON
C17 C21 C23 C24 C26 C27 C32 = Cap: Capacitor; Value: 10nF
C22 C28-C30 C33 = CAP: Capacitor
C34 = Cap Pol1: Polarized Capacitor (Radial); Value: 10uF
C85 = CAP: Capacitor; Value: 100pF
D1 D2 = Diode: Default Diode; Code - JEDEC: DO-214-AB
JP2 JP6 JP11 JP18 JP19 = JP2
JP7 JP8 JP10 = Jumper3
L1 = Inductor: Value: 100uH
R32 R43 R137 R138 = res1: Resistor; Value: 1K
R37-R41 R77 R78 R81 R86 R88 = Res1: Resistor; Value: 1K
SW1 SW2 = SW-SPDT: SPDT Subminiature Toggle Switch, Right Angle Mounting, Vertical Actuation; Revision 1: Jul-2002: Re-released for DXP Platform.; Revision 2: 17-Dec-2003: Schematic revised, PCB Footprint replaced.
TP1 = TP
U11 = BARRACUDA_256K
X1 = MC306
X2 = CRYSTAL

## Sheet Peripherals.SchDoc
size A4; Revision: B.4(PCB.SCH)
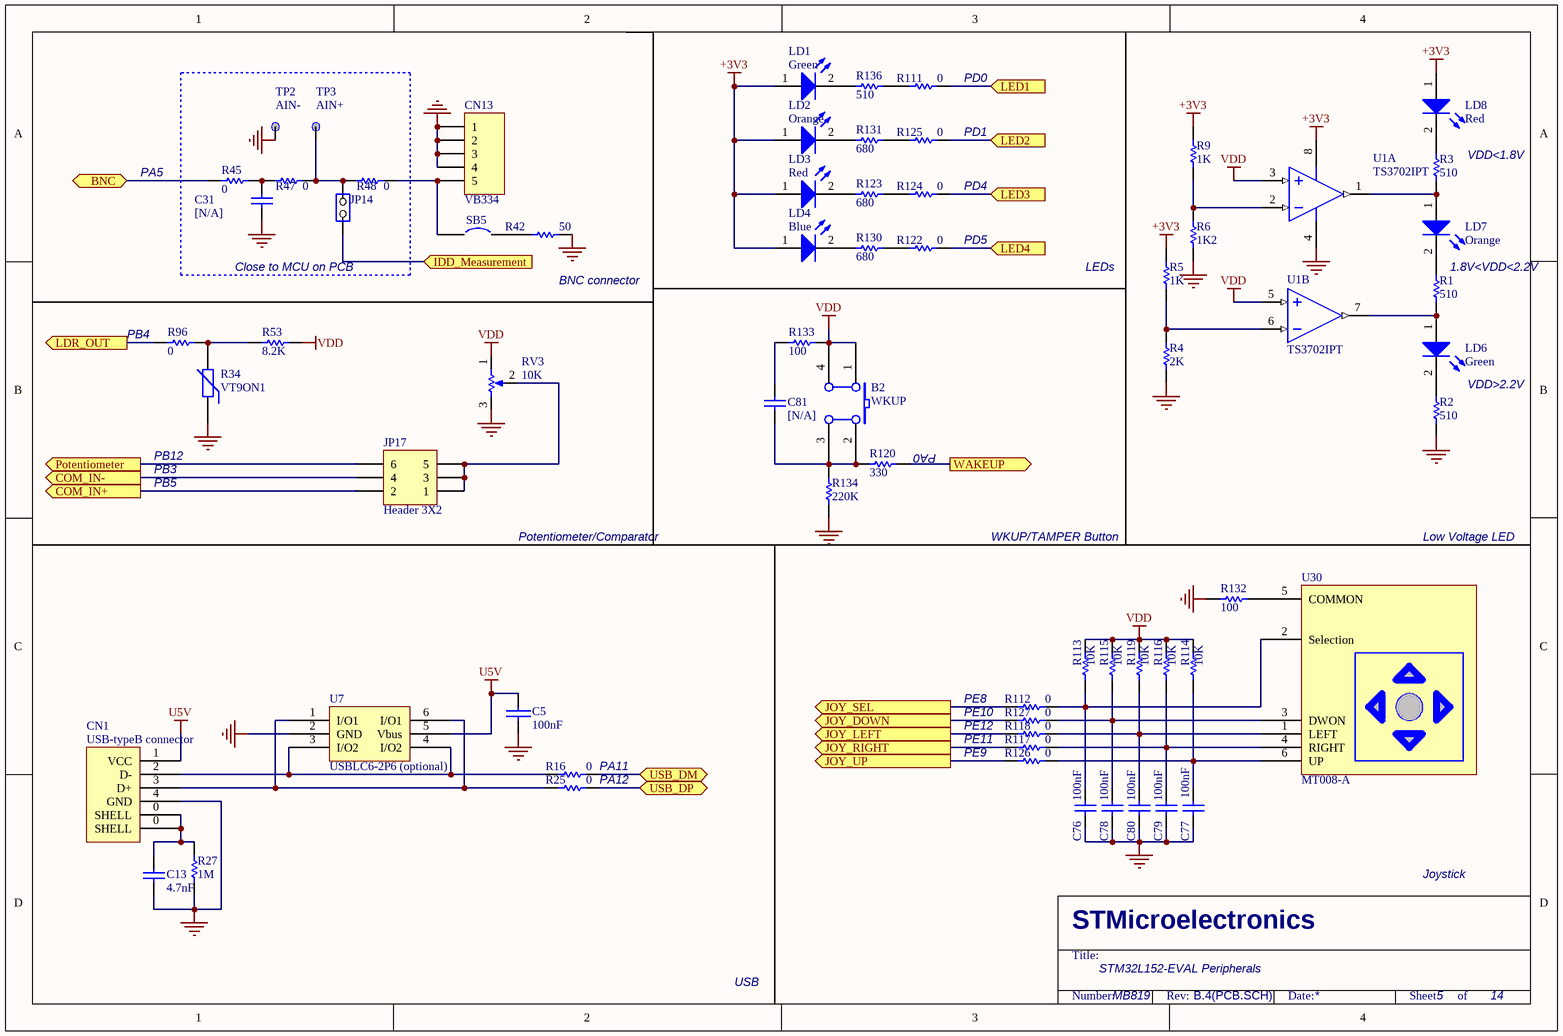
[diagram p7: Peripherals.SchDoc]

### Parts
B2  WKUP  [PB10]
C5  100nF  [0402C]
C13  4.7nF  [0603C]
C31  [N/A]  [0603C]
C76  100nF  [0402C]
C77  100nF  [0402C]
C78  100nF  [0402C]
C79  100nF  [0402C]
C80  100nF  [0402C]
C81  [N/A]  [0603C]
CN1  USB-typeB connector  [USB-B]
CN13  VB334  [VB334]
JP14  (no value)  [SIP2]
JP17  Header 3X2  [2*3P]
LD1  Green  [0603D]
LD2  Orange  [0603D]
LD3  Red  [0603D]
LD4  Blue  [0603D]
LD6  Green  [0603D]
LD7  Orange  [0603D]
LD8  Red  [0603D]
R1  510  [0402R]
R2  510  [0402R]
R3  510  [0402R]
R4  2K  [0603R]
R5  1K  [0402R]
R6  1K2  [0603R]
R9  1K  [0402R]
R16  0  [0603R]
R25  0  [0603R]
R27  1M  [0603R]
R34  VT9ON1
R42  50  [0603R]
R45  0  [0603R]
R47  0  [0603R]
R48  0  [0603R]
R53  8.2K  [0402R]
R96  0  [0603R]
R111  0  [0603R]
R112  0  [0603R]
R113  10K  [0402R]
R114  10K  [0402R]
R115  10K  [0402R]
R116  10K  [0402R]
R117  0  [0603R]
R118  0  [0603R]
R119  10K  [0402R]
R120  330  [0603R]
R122  0  [0603R]
R123  680  [0402R]
R124  0  [0603R]
R125  0  [0603R]
R126  0  [0603R]
R127  0  [0603R]
R130  680  [0402R]
R131  680  [0402R]
R132  100  [0603R]
R133  100  [0603R]
R134  220K  [0603R]
R136  510  [0402R]
RV3  10K  [3296W]
SB5  (no value)  [JP2_SMD]
TP2  AIN-  [TP]
TP3  AIN+  [TP]
U1  TS3702IPT  [TSSOP8(6.4)]  (parts A,B of 2)
U7  USBLC6-2P6 (optional)  [SOT-666]
U30  MT008-A  [JOY]

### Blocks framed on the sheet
Close to MCU on PCB: C31 JP14 R45 R47 R48 TP2 TP3

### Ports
BNC (bidir), COM_IN+ (out), COM_IN- (out), IDD_Measurement (in), JOY_DOWN (out), JOY_LEFT (out), JOY_RIGHT (out), JOY_SEL (out), JOY_UP (out), LDR_OUT (out), LED1 (in), LED2 (in), LED3 (in), LED4 (in), Potentiometer (out), USB_DM (bidir), USB_DP (bidir), WAKEUP (out)

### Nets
+3V3: LD1.1(A) LD2.1(A) LD3.1(A) LD4.1(A) LD8.1(A) R5.2 R9.2 U1.8(V+)
GND: C5.2 C13.1 C31.1 C76.1 C77.1 C78.1 C79.1 C80.1 CN1.4(GND) CN13.1 CN13.2 CN13.3 CN13.4 R2.2 R4.1 R6.1 R27.1 R34.1 R42.2 R132.1 R134.2 RV3.3(TOP) TP2.1 U1.4(V-) U7.2(GND)
U5V: C5.1 CN1.1(VCC) U7.5(Vbus)
VDD: B2.1(A0) B2.4(A1) R53.2 R113.1 R114.2 R115.2 R116.2 R119.2 R133.1 RV3.1(BOT) U1.3(IN+) U1.5(IN+)
PA0: R120.2 ; port WAKEUP
PA5: R45.1 ; port BNC
PA11: R16.1 ; port USB_DM
PA12: R25.1 ; port USB_DP
PB3: JP17.4 ; port COM_IN-
PB5: JP17.2 ; port COM_IN+
PB12: JP17.6 ; port Potentiometer
PD0: R111.1 ; port LED1
PD1: R125.1 ; port LED2
PE8: R112.2 ; port JOY_SEL
PE9: R126.2 ; port JOY_UP
PE10: R127.2 ; port JOY_DOWN
PE11: R117.2 ; port JOY_RIGHT
PE12: R118.2 ; port JOY_LEFT
NetB2_2: B2.2(B0) B2.3(B1) C81.2 R120.1 R134.1
NetC13_2: C13.2 CN1.0(SHELL) R27.2
NetC25_1: JP14.2(NO) ; port IDD_Measurement
NetC31_2: C31.2 R45.2 R47.1
NetC76_2: C76.2 R112.1 R113.2 U30.2(Selection)
NetC77_2: C77.2 R114.1 R126.1 U30.6(UP)
NetC78_2: C78.2 R115.1 R127.1 U30.3(DWON)
NetC79_2: C79.2 R116.1 R117.1 U30.4(RIGHT)
NetC80_2: C80.2 R118.1 R119.1 U30.1(LEFT)
NetC81_1: C81.1 R133.2
NetCN1_2: CN1.2(D-) R16.2 U7.3(I/O2) U7.4(I/O2)
NetCN1_3: CN1.3(D+) R25.2 U7.1(I/O1) U7.6(I/O1)
NetCN13_5: CN13.5 R48.2 SB5.1
NetJP10_1: R96.2 ; port LDR_OUT
NetJP14_1: JP14.1(COMMON) R47.2 R48.1 TP3.1
NetJP17_1: JP17.1 JP17.3 JP17.5 RV3.2(TAP)
NetJP18_1: R124.1 ; port LED3
NetJP19_1: R122.1 ; port LED4
NetLD1_2: LD1.2(K) R136.2
NetLD2_2: LD2.2(K) R131.2
NetLD3_2: LD3.2(K) R123.2
NetLD4_2: LD4.2(K) R130.2
NetLD6_1: LD6.1(A) R1.2 U1.7(OUT)
NetLD6_2: LD6.2(K) R2.1
NetLD7_1: LD7.1(A) R3.2 U1.1(OUT)
NetLD7_2: LD7.2(K) R1.1
NetLD8_2: LD8.2(K) R3.1
NetR4_2: R4.2 R5.1 U1.6(IN-)
NetR6_2: R6.2 R9.1 U1.2(IN-)
NetR34_2: R34.2 R53.1 R96.1
NetR42_1: R42.1 SB5.2
NetR111_2: R111.2 R136.1
NetR122_2: R122.2 R130.1
NetR123_1: R123.1 R124.2
NetR125_2: R125.2 R131.1
NetR132_2: R132.2 U30.5(COMMON)

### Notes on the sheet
- (near R111) PD0
- PA5
- (near R125) PD1
- VDD<1.8V
- (near R124) PD4
- (near R122) PD5
- (near R42) BNC connector
- LEDs
- (near R1) 1.8V<VDD<2.2V
- (near R96) PB4
- (near R120) PA0
- VDD>2.2V
- PB12
- PB3
- PB5
- Potentiometer/Comparator
- WKUP/TAMPER Button
- Low Voltage LED
- PE10
- PE8
- PA12
- PA11
- PE9
- PE11
- PE12
- Joystick
- USB
- STM32L152-EVAL Peripherals
- MB819
- 5
- 14

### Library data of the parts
B2 = SW PUSHBUTTON: SE PUSHBUTTON
C5 = CAP: Capacitor
C13 C76-C81 = CAP: Capacitor; Value: 100pF
C31 = cap: Capacitor; Value: 100pF
CN1 = USB-B
CN13 = Header 5: Header, 5-Pin
JP14 = JP2
JP17 = Header 3X2: Header, 3-Pin, Dual row
LD1-LD4 LD6-LD8 = LED2: Typical RED, GREEN, YELLOW, AMBER GaAs LED
R1-R4 R6 R16 R25 R27 R42 R45 R47 R48 R53 R96 R111-R120 R122-R127 R130-R133 R136 = Res1: Resistor; Value: 1K
R5 R9 = Res1: Resistor
R34 = Res Varistor: Varistor (Voltage-Sensitive Resistor)
R134 = res1: Resistor; Value: 1K
RV3 = RV
SB5 = Circuit Breaker
TP2 TP3 = TP
U1 = LM393PT
U7 = USBLC6-2
U30 = MT-008A

## Sheet Power.SchDoc
size A4; Revision: B.4(PCB.SCH)
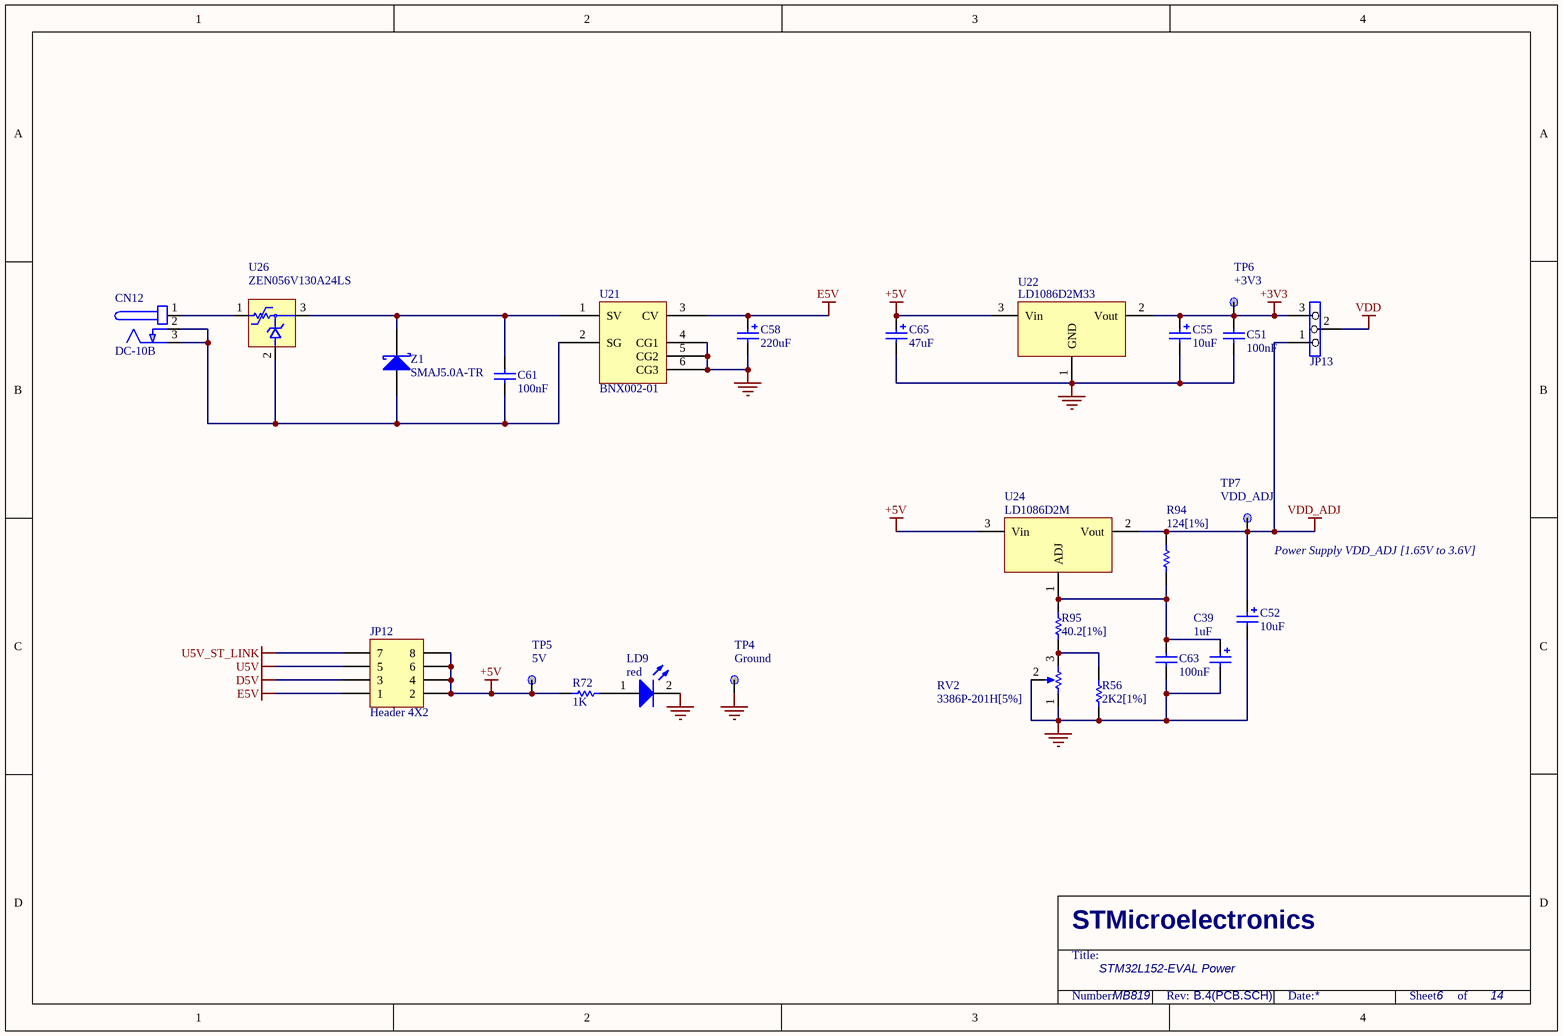
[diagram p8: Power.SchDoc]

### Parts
C39  1uF  [TAN-A]
C51  100nF  [0402C]
C52  10uF  [TAN-A]
C55  10uF  [TAN-A]
C58  220uF  [C310M]
C61  100nF  [0402C]
C63  100nF  [0402C]
C65  47uF  [C200M]
CN12  DC-10B  [DC10B]
JP12  Header 4X2  [2*4P]
JP13  (no value)  [SIP3]
LD9  red  [0603D]
R56  2K2[1%]  [0603R]
R72  1K  [0402R]
R94  124[1%]  [0603R]
R95  40.2[1%]  [0603R]
RV2  3386P-201H[5%]  [3296W]
TP4  Ground  [TP]
TP5  5V  [TP]
TP6  +3V3  [TP]
TP7  VDD_ADJ  [TP]
U21  BNX002-01  [BNX001]
U22  LD1086D2M33  [D2PAK/A]
U24  LD1086D2M  [D2PAK/A]
U26  ZEN056V130A24LS  [polyzen]
Z1  SMAJ5.0A-TR  [1R1C]

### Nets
+3V3: C51.1 C55.1 JP13.3 TP6.1 U22.2(Vout)
+5V: C65.1 JP12.2 JP12.4 JP12.6 JP12.8 R72.2 TP5.1 U22.3(Vin) U24.3(Vin)
D5V: JP12.3
E5V: C58.1 JP12.1 U21.3(CV)
GND: C39.2 C51.2 C52.2 C55.2 C58.2 C63.2 C65.2 LD9.2(K) R56.2 RV2.1(BOT) RV2.2(TAP) TP4.1 U21.4(CG1) U21.5(CG2) U21.6(CG3) U22.1(GND)
U5V: JP12.5
U5V_ST_LINK: JP12.7
VDD: JP13.2
VDD_ADJ: C52.1 JP13.1 R94.2 TP7.1 U24.2(Vout)
NetC39_1: C39.1 C63.1 R94.1 R95.1 U24.1(ADJ)
NetC61_1: C61.1 U21.1(SV) U26.3 Z1.2(K)
NetC61_2: C61.2 CN12.2(GND) CN12.3(GND) U21.2(SG) U26.2 Z1.1(A)
NetCN12_1: CN12.1(+) U26.1
NetLD9_1: LD9.1(A) R72.1
NetR56_1: R56.1 R95.2 RV2.3(TOP)

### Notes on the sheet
- Power Supply VDD_ADJ [1.65V to 3.6V]
- STM32L152-EVAL Power
- MB819
- 6
- 14

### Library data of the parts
C39 C65 = Cap Pol1: as C34 on sheet MCU
C51 C63 = Cap: Capacitor; Value: 10nF
C52 C55 = Cap Pol1: Polarized Capacitor (Radial)
C58 = Cap Pol1: Polarized Capacitor (Radial); Value: 47uF
C61 = CAP: Capacitor; Value: 100pF
CN12 = PJ202A
JP12 = Header 4X2: Header, 4-Pin, Dual row
JP13 = Jumper3
LD9 = LED2: as LD1 on sheet Peripherals
R56 R94 R95 = Res1: Resistor; Value: 1K
R72 = res1: Resistor
RV2 = RV
TP4-TP7 = TP
U21 = BNX002
U22 = VOLTREG1
U24 = LD1086
Z1 = D Schottky: Schottky Diode; Code - JEDEC: DO-214-AA

## Sheet RS232_IrDA.SCHDOC
size A4; Revision: B.4(PCB.SCH)
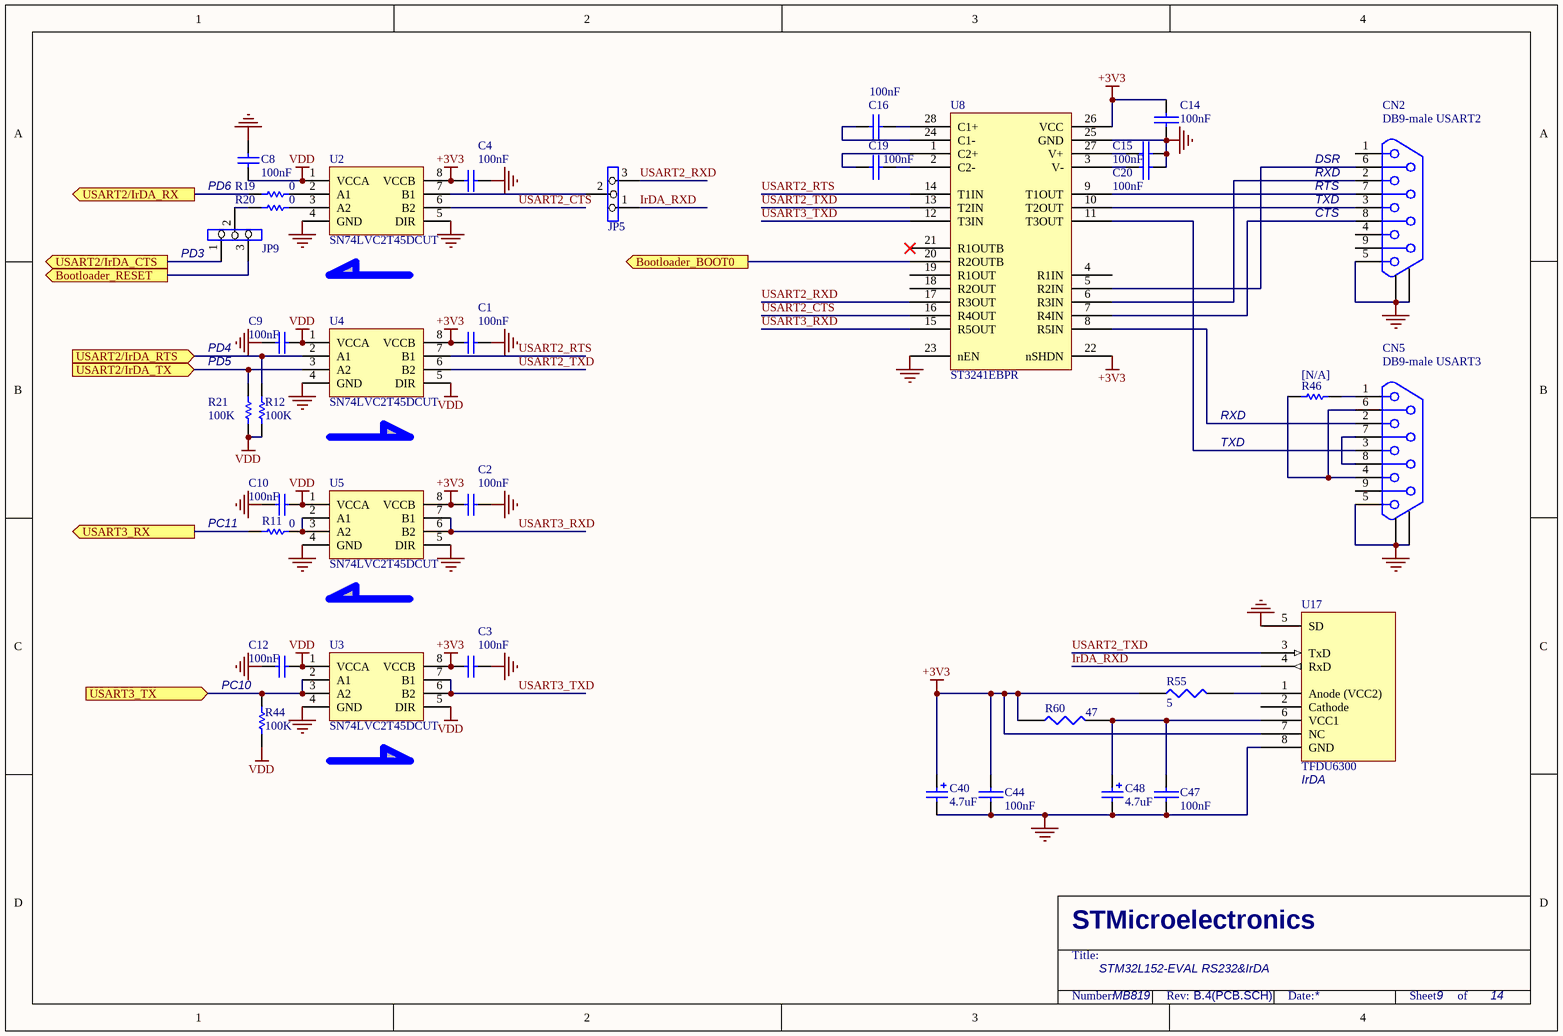
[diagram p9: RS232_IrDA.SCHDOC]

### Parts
C1  100nF  [0402C]
C2  100nF  [0402C]
C3  100nF  [0402C]
C4  100nF  [0402C]
C8  100nF  [0402C]
C9  100nF  [0402C]
C10  100nF  [0402C]
C12  100nF  [0402C]
C14  100nF  [0402C]
C15  100nF  [0402C]
C16  100nF  [0402C]
C19  100nF  [0402C]
C20  100nF  [0402C]
C40  4.7uF  [TAN-A]
C44  100nF  [0402C]
C47  100nF  [0402C]
C48  4.7uF  [TAN-A]
CN2  DB9-male USART2  [DB9/M]
CN5  DB9-male USART3  [DB9/M]
JP5  (no value)  [SIP3]
JP9  (no value)  [SIP3]
R11  0  [0603R]
R12  100K  [0603R]
R19  0  [0603R]
R20  0  [0603R]
R21  100K  [0603R]
R44  100K  [0603R]
R46  [N/A]  [0603R]
R55  5  [0603R]
R60  47  [0603R]
U2  SN74LVC2T45DCUT  [VSSOP8]
U3  SN74LVC2T45DCUT  [VSSOP8]
U4  SN74LVC2T45DCUT  [VSSOP8]
U5  SN74LVC2T45DCUT  [VSSOP8]
U8  ST3241EBPR  [SSOP28]
U17  TFDU6300  [IR_VISHAY3]

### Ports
Bootloader_BOOT0 (out), Bootloader_RESET (out), USART2/IrDA_CTS (out), USART2/IrDA_RTS (in), USART2/IrDA_RX (out), USART2/IrDA_TX (in), USART3_RX (out), USART3_TX (in)

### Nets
+3V3: C1.2 C2.2 C3.2 C4.2 C14.2 C40.1 C44.1 R55.1 R60.1 U2.8(VCCB) U3.8(VCCB) U4.8(VCCB) U5.8(VCCB) U8.22(nSHDN) U8.26(VCC) U17.7(NC)
GND: C1.1 C2.1 C3.1 C4.1 C8.2 C9.1 C10.1 C12.1 C14.1 C15.2 C20.2 C40.2 C44.2 C47.2 C48.2 CN2.0 CN2.5 CN5.0 CN5.5 U2.4(GND) U2.5(DIR) U3.4(GND) U4.4(GND) U5.4(GND) U5.5(DIR) U8.23(nEN) U8.25(GND) U17.5(SD) U17.8(GND)
VDD: C8.1 C9.2 C10.2 C12.2 R12.2 R21.2 R44.2 U2.1(VCCA) U3.1(VCCA) U3.5(DIR) U4.1(VCCA) U4.5(DIR) U5.1(VCCA)
IrDA_RXD: JP5.1 U17.4(RxD)
PD3: JP9.1 ; port USART2/IrDA_CTS
PD4: R12.1 U4.2(A1) ; port USART2/IrDA_RTS
PD5: R21.1 U4.3(A2) ; port USART2/IrDA_TX
PD6: R19.1 ; port USART2/IrDA_RX
USART2_CTS: U2.6(B2) U8.16(R4OUT)
USART2_RTS: U4.7(B1) U8.14(T1IN)
USART2_RXD: JP5.3 U8.17(R3OUT)
USART2_TXD: U4.6(B2) U8.13(T2IN) U17.3(TxD)
USART3_RXD: U5.6(B2) U5.7(B1) U8.15(R5OUT)
USART3_TXD: U3.6(B2) U3.7(B1) U8.12(T3IN)
NetC15_1: C15.1 U8.27(V+)
NetC16_1: C16.1 U8.24(C1-)
NetC16_2: C16.2 U8.28(C1+)
NetC19_1: C19.1 U8.1(C2+)
NetC19_2: C19.2 U8.2(C2-)
NetC20_1: C20.1 U8.3(V-)
NetC47_1: C47.1 C48.1 R60.2 U17.6(VCC1)
NetCN2_2: CN2.2 U8.6(R3IN)
NetCN2_3: CN2.3 U8.10(T2OUT)
NetCN2_6: CN2.6 U8.5(R2IN)
NetCN2_7: CN2.7 U8.9(T1OUT)
NetCN2_8: CN2.8 U8.7(R4IN)
NetCN5_1: CN5.1 R46.2
NetCN5_2: CN5.2 U8.8(R5IN)
NetCN5_3: CN5.3 U8.11(T3OUT)
NetCN5_4: CN5.4 CN5.6 R46.1
NetCN5_7: CN5.7 CN5.8
NetD2_2: JP9.3 ; port Bootloader_RESET
NetJP5_2: JP5.2 U2.7(B1)
NetJP7_3: R44.1 U3.2(A1) U3.3(A2) ; port USART3_TX
NetJP8_3: R11.1 ; port USART3_RX
NetJP9_2: JP9.2 R20.1
NetR11_2: R11.2 U5.2(A1) U5.3(A2)
NetR19_2: R19.2 U2.2(A1)
NetR20_2: R20.2 U2.3(A2)
NetR55_2: R55.2 U17.1(Anode_(VCC2))
NetR138_2: U8.20(R2OUTB) ; port Bootloader_BOOT0

Not connected (* = marked no-connect by the designer): CN2 1 4 9; CN5 9; U8 4(R1IN) 18(R2OUT) 19(R1OUT) 21(R1OUTB)*; U17 2(Cathode)

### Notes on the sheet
- (near CN2) RXD
- (near CN2) DSR
- PD6
- (near CN2) RTS
- (near CN2) TXD
- (near CN2) CTS
- (near JP9) PD3
- PD5
- PD4
- RXD
- TXD
- PC11
- PC10
- (near U17) IrDA
- STM32L152-EVAL RS232&IrDA
- MB819
- 9
- 14

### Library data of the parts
C1-C4 C8-C10 C12 = CAP: Capacitor; Value: 100pF
C14-C16 C19 C20 C44 C47 = CAP: Capacitor
C40 C48 = Cap Pol1: as C66 on sheet Audio
CN2 CN5 = DB9
JP5 JP9 = Jumper3
R11 R12 R19-R21 R44 = Res1: Resistor; Value: 1K
R46 = res1: Resistor; Value: 1K
R55 R60 = RES1
U8 = ST3241
U17 = TFDU4300

## Sheet ST_LINK.SCHDOC
size A4; Revision: B.4(PCB.SCH)
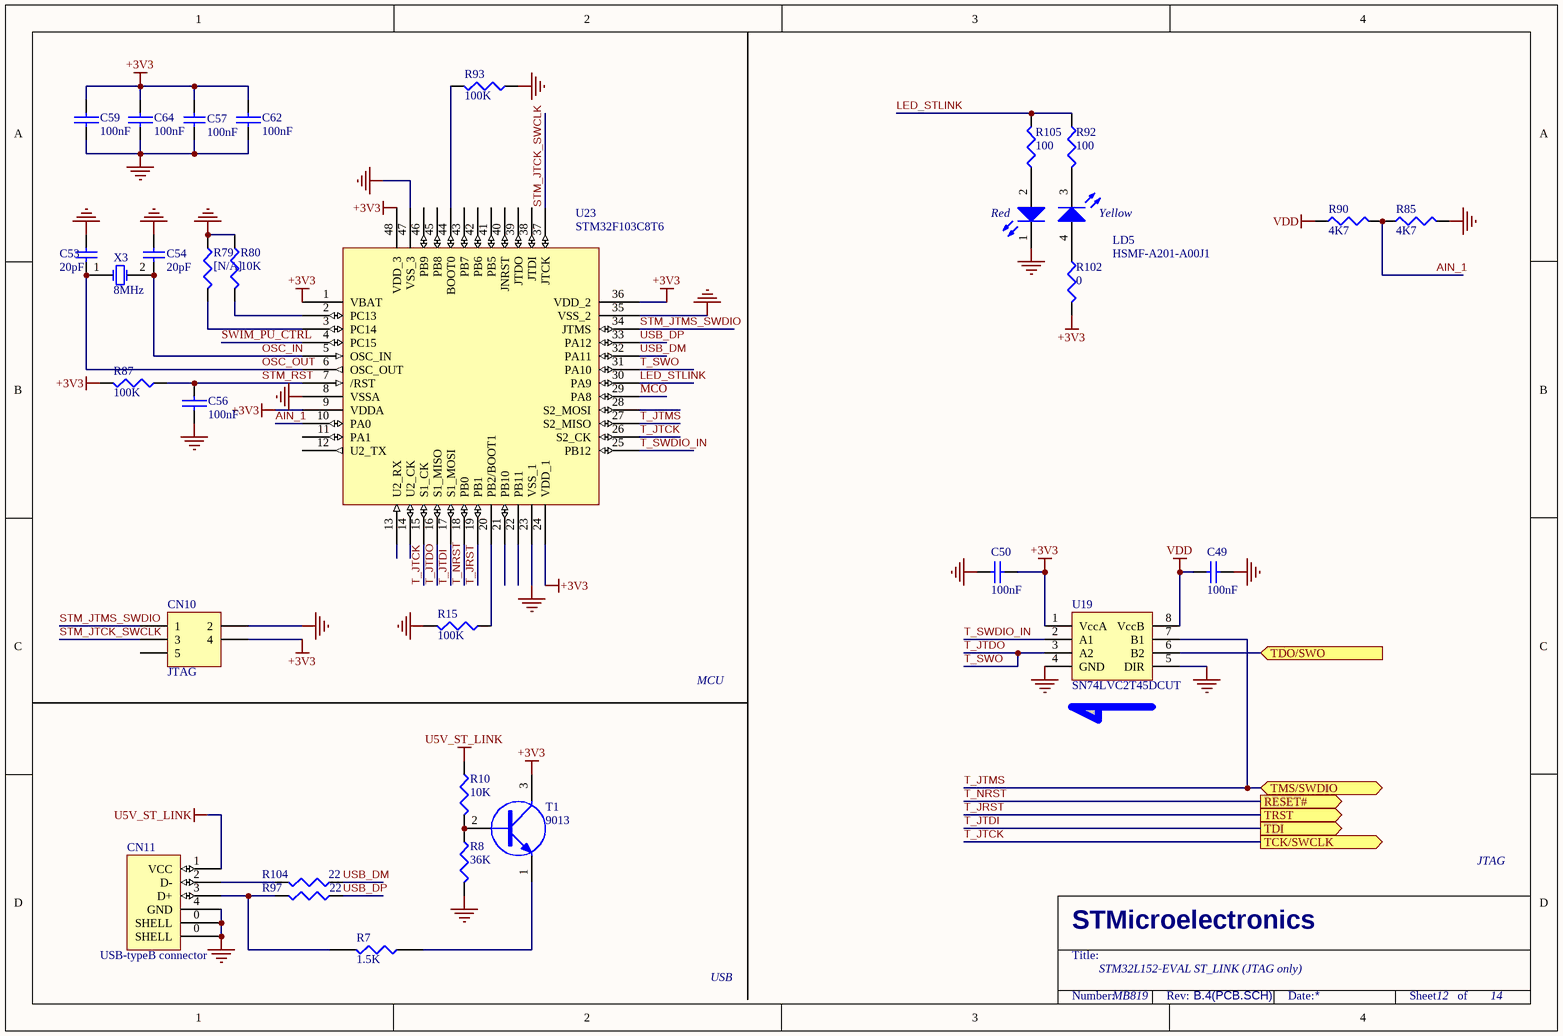
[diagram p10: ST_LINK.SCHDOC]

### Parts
C49  100nF  [0402C]
C50  100nF  [0402C]
C53  value 20pF  [0603R]  (hidden comment: Cap)
C54  value 20pF  [0603R]  (hidden comment: Cap)
C56  100nF  [0402C]
C57  100nF  [0402C]
C59  100nF  [0402C]
C62  100nF  [0402C]
C64  100nF  [0402C]
CN10  JTAG  [HDR2X3]
CN11  USB-typeB connector  [USB-B]
LD5  HSMF-A201-A00J1
R7  1.5K  [0603]
R8  36K  [0603]
R10  10K  [0603]
R15  100K  [0603R]
R79  [N/A]  [0603]
R80  10K  [0603]
R85  4K7  [0402R]
R87  100K  [0603R]
R90  4K7  [0402R]
R92  100  [0402R]
R93  100K  [0603R]
R97  22  [0603R]
R102  0  [0402R]
R104  22  [0603R]
R105  100  [0402R]
T1  9013  [SOT-23]
U19  SN74LVC2T45DCUT  [VSSOP8]
U23  STM32F103C8T6  [LQFP48]
X3  8MHz  [SMT_XTAL]

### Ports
RESET# (out), TCK/SWCLK (out), TDI (out), TDO/SWO (in), TMS/SWDIO (bidir), TRST (out)

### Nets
+3V3: C50.2 C57.1 C59.2 C62.2 C64.2 CN10.4 R87.2 R102.2 T1.3(C) U19.1(VccA) U23.1(VBAT) U23.9(VDDA) U23.24(VDD_1) U23.36(VDD_2) U23.48(VDD_3)
GND: C49.2 C50.1 C53.1 C54.1 C56.1 C57.2 C59.1 C62.1 C64.1 CN10.2 CN11.0(SHELL) CN11.4(GND) LD5.1(RED_cathode) R8.2 R15.2 R79.1 R80.1 R85.2 R93.1 U19.4(GND) U19.5(DIR) U23.8(VSSA) U23.23(VSS_1) U23.35(VSS_2) U23.47(VSS_3)
U5V_ST_LINK: CN11.1(VCC) R10.1
VDD: C49.1 R90.1 U19.8(VccB)
AIN_1: R85.1 R90.2 U23.10(PA0)
LED_STLINK: R92.1 R105.2 U23.30(PA9)
MCO: U23.29(PA8)
OSC_IN: C54.2 U23.5(OSC_IN) X3.2(OSC2)
OSC_OUT: C53.2 U23.6(OSC_OUT) X3.1(OSC1)
PB3: U19.6(B2) ; port TDO/SWO
STM_JTCK_SWCLK: CN10.3 U23.37(JTCK)
STM_JTMS_SWDIO: CN10.1 U23.34(JTMS)
STM_RST: C56.2 R87.1 U23.7(/RST)
SWIM_PU_CTRL: U23.4(PC15)
T_JRST: U23.19(PB1) ; port TRST
T_JTCK: U23.15(S1_CK) U23.26(S2_CK) ; port TCK/SWCLK  [project net PA14]
T_JTDI: U23.17(S1_MOSI) ; port TDI  [project net PA15]
T_JTDO: U19.3(A2) U23.16(S1_MISO) U23.31(PA10)  [also labelled T_SWO]
T_JTMS: U19.7(B1) U23.27(S2_MISO) ; port TMS/SWDIO  [project net PA13]
T_NRST: U23.18(PB0) ; port RESET#  [project net RESET#]
T_SWDIO_IN: U19.2(A1) U23.25(PB12)
USB_DM: R104.1 U23.32(PA11)
USB_DP: R97.1 U23.33(PA12)
NetCN11_2: CN11.2(D-) R104.2
NetCN11_3: CN11.3(D+) R7.2 R97.2
NetLD5_2: LD5.2(Red_anode) R105.1
NetLD5_3: LD5.3(YellowGreen_cathode) R92.2
NetLD5_4: LD5.4(YellowGreen_anode) R102.1
NetR7_1: R7.1 T1.1(E)
NetR8_1: R8.1 R10.2 T1.2(B)
NetR15_1: R15.1 U23.20(PB2/BOOT1)
NetR79_2: R79.2 U23.3(PC14)
NetR80_2: R80.2 U23.2(PC13)
NetR93_2: R93.2 U23.44(BOOT0)

Not connected (* = marked no-connect by the designer): CN10 5; U23 11(PA1) 12(U2_TX) 13(U2_RX) 14(U2_CK) 21(PB10) 22(PB11) 28(S2_MOSI) 38(JTDI) 39(JTDO) 40(JNRST) 41(PB5) 42(PB6) 43(PB7) 45(PB8) 46(PB9)

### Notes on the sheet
- MCU
- JTAG
- USB
- STM32L152-EVAL ST_LINK (JTAG only)
- MB819
- 12
- 14

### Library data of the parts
C49 C50 = CAP: Capacitor; Value: 100pF
C53 C54 = Cap: Capacitor
C56 C59 C62 C64 = CAP
C57 = Cap: Capacitor; Value: 10nF
CN10 = Header 3X2: Header, 3-Pin, Dual row
R7 R15 R85 R87 R90 R92 R93 R97 R102 R104 R105 = RES1
R8 R10 R79 R80 = R: Right: 20; Bottom: 30
T1 = NPN
U23 = STM32F10x(48pin)
X3 = XTAL: Crystal Oscillator

## Sheet TemSensor.SCHDOC
size A4; Revision: B.4(PCB.SCH)
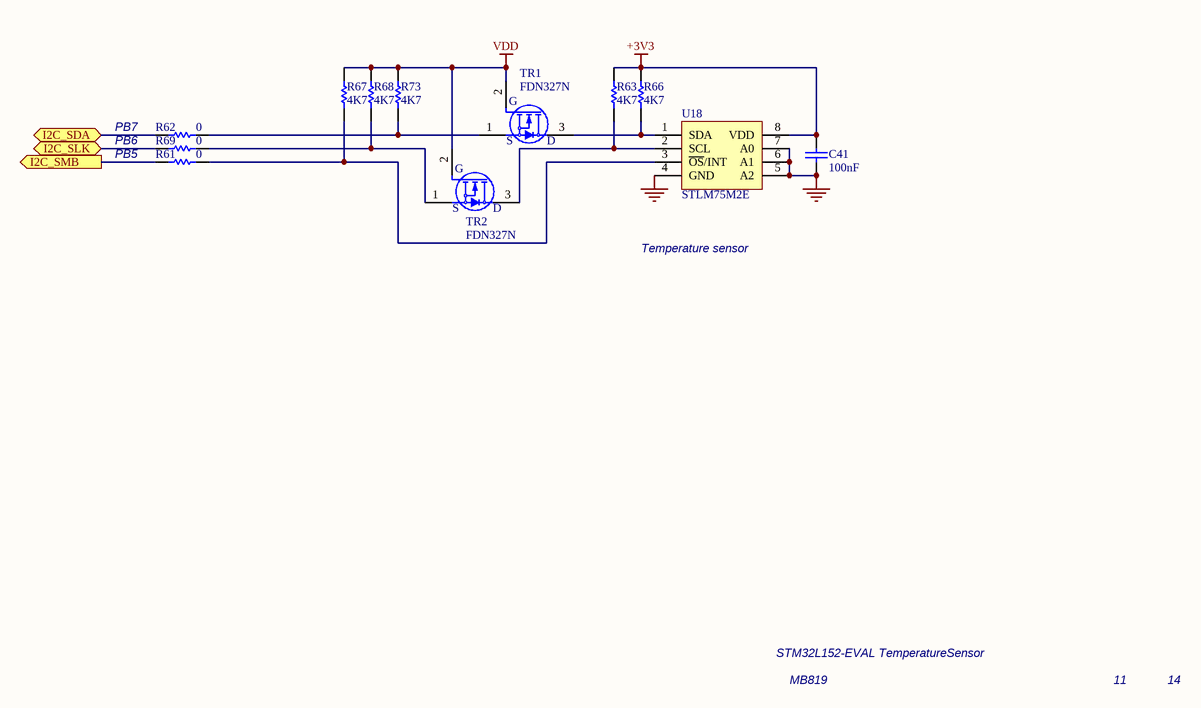
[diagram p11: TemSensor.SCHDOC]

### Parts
C41  100nF  [0402C]
R61  0  [0603R]
R62  0  [0603R]
R63  4K7  [0402R]
R66  4K7  [0402R]
R67  4K7  [0402R]
R68  4K7  [0402R]
R69  0  [0603R]
R73  4K7  [0402R]
TR1  FDN327N  [SOT-23]
TR2  FDN327N  [SOT-23]
U18  STLM75M2E  [SO8]

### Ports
I2C_SDA (bidir), I2C_SLK (bidir), I2C_SMB (out)

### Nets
+3V3: C41.2 R63.2 R66.2 U18.8(VDD)
GND: C41.1 U18.4(GND) U18.5(A2) U18.6(A1) U18.7(A0)
VDD: R67.2 R68.2 R73.2 TR1.2(G) TR2.2(G)
PB6: R69.1 ; port I2C_SLK
PB7: R62.1 ; port I2C_SDA
NetJP11_2: R61.2 ; port I2C_SMB
NetR61_1: R61.1 R67.1 U18.3(~{OS}/INT)
NetR62_2: R62.2 R73.1 TR1.1(S)
NetR63_1: R63.1 TR2.3(D) U18.2(SCL)
NetR66_1: R66.1 TR1.3(D) U18.1(SDA)
NetR68_1: R68.1 R69.2 TR2.1(S)

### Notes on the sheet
- PB7
- PB6
- PB5
- Temperature sensor
- STM32L152-EVAL TemperatureSensor
- MB819
- 11
- 14

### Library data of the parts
C41 = cap: Capacitor; Value: 100pF
R61-R63 R66-R69 R73 = Res1: Resistor; Value: 1K
TR1 TR2 = 2N7000
U18 = STLM75DW2F

## Sheet Touch Sensing.SchDoc
size A4; Revision: B.4(PCB.SCH)
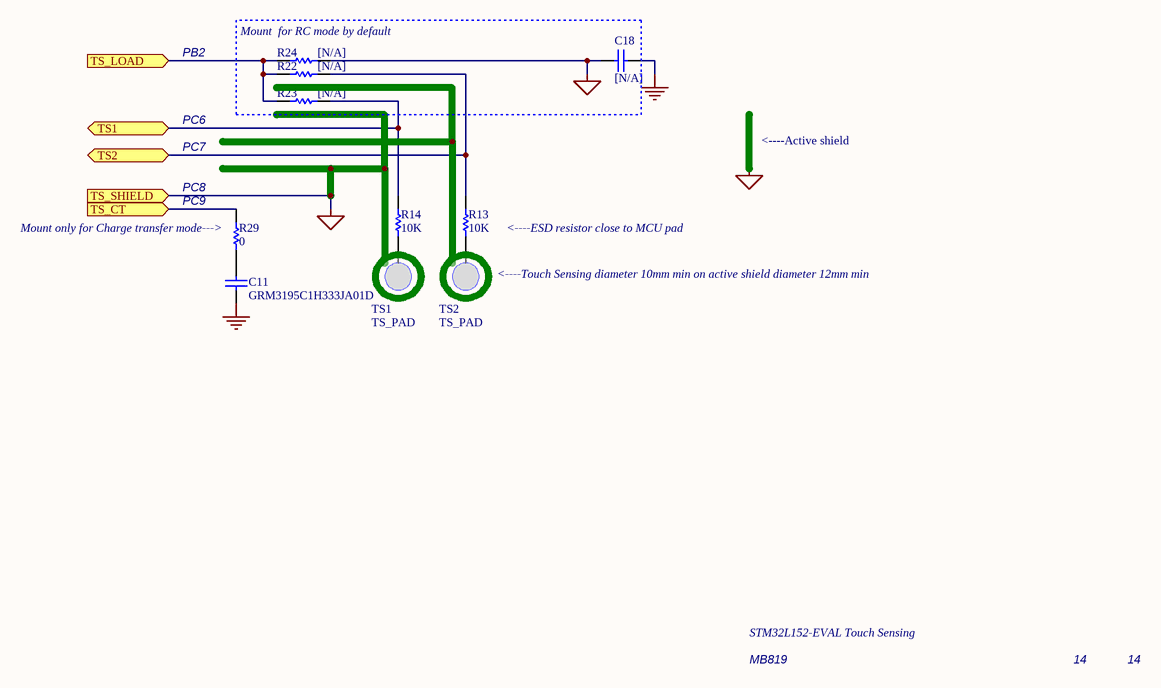
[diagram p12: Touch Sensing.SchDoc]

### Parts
C11  GRM3195C1H333JA01D  [1206C]
C18  [N/A]  [0603C]
R13  10K  [0603R]
R14  10K  [0603R]
R22  [N/A]  [0603R]
R23  [N/A]  [0603R]
R24  [N/A]  [0603R]
R29  0  [0603R]
TS1  TS_PAD  [TS_PAD]
TS2  TS_PAD  [TS_PAD]

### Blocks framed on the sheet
Mount  for RC mode by default: C18 R22-R24

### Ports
TS1 (bidir), TS2 (bidir), TS_CT (in), TS_LOAD (in), TS_SHIELD (in)

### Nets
GND: C11.1 C18.2
TS_SHIELD: C18.1 R24.1 ; port TS_SHIELD  [project net PC8]
PB2: R22.2 R23.2 R24.2 ; port TS_LOAD
PC6: R14.1 R23.1 ; port TS1
PC7: R13.1 R22.1 ; port TS2
PC9: R29.1 ; port TS_CT
NetC11_2: C11.2 R29.2
NetR13_2: R13.2 TS2.1
NetR14_2: R14.2 TS1.1

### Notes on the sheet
- PB2
- PC6
- PC7
- <----Active shield
- (near R29) Mount only for Charge transfer mode--->
- (near R29) PC8
- (near R29) PC9
- <----ESD resistor close to MCU pad
- <----Touch Sensing diameter 10mm min on active shield diameter 12mm min
- STM32L152-EVAL Touch Sensing
- MB819
- 14

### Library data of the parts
C11 C18 = CAP: Capacitor; Value: 100pF
R13 R14 R22-R24 R29 = Res1: Resistor; Value: 1K

## Sheet IDD_measurement.SchDoc
size A4; Revision: B.4(SCH.PCB)
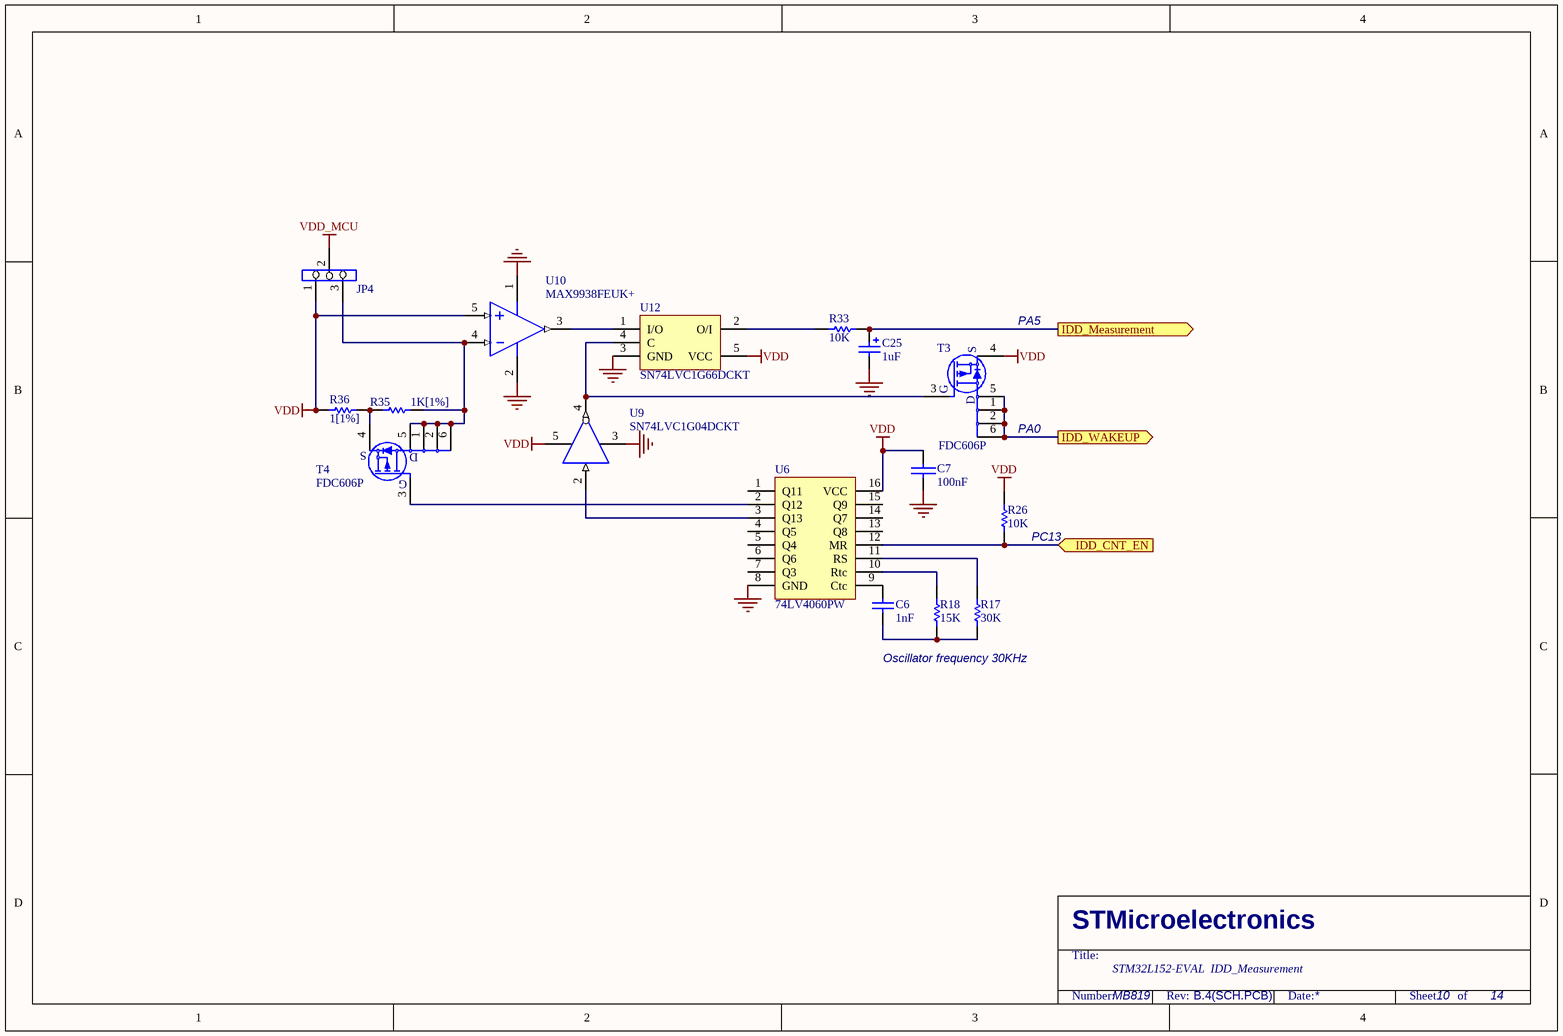
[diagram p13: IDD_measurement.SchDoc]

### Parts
C6  1nF  [0603C]
C7  100nF  [0402C]
C25  1uF  [0603C]
JP4  (no value)  [SIP3]
R17  30K  [0603R]
R18  15K  [0603R]
R26  10K  [0402R]
R33  10K  [0402R]
R35  1K[1%]  [0603R]
R36  1[1%]  [0603R]
T3  FDC606P  [SOT23-6L]
T4  FDC606P  [SOT23-6L]
U6  74LV4060PW  [TSSOP16]
U9  SN74LVC1G04DCKT  [PDSO-G5]
U10  MAX9938FEUK+  [SOT-23-5L]
U12  SN74LVC1G66DCKT  [PDSO-G5]

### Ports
IDD_CNT_EN (in), IDD_Measurement (out), IDD_WAKEUP (out)

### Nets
GND: C7.2 C25.2 U6.8(GND) U9.3(GND) U10.1(GND) U10.2(GND) U12.3(GND)
VDD: C7.1 JP4.1 R26.1 R36.2 T3.4(S) U6.16(VCC) U9.5(VCC) U10.5(Vp) U12.5(VCC)
VDD_MCU: JP4.2
PA0: T3.1(D) T3.2(D) T3.5(D) T3.6(D) ; port IDD_WAKEUP
PC13: R26.2 U6.12(MR) ; port IDD_CNT_EN
NetC6_1: C6.1 U6.9(Ctc)
NetC6_2: C6.2 R17.2 R18.2
NetC25_1: C25.1 R33.2 ; port IDD_Measurement
NetJP4_3: JP4.3 R35.1 T4.1(D) T4.2(D) T4.5(D) T4.6(D) U10.4(Vm)
NetR17_1: R17.1 U6.11(RS)
NetR18_1: R18.1 U6.10(Rtc)
NetR33_1: R33.1 U12.2(O/I)
NetR35_2: R35.2 R36.1 T4.4(S)
NetT3_3: T3.3(G) U9.4(1Y) U12.4(C)
NetT4_3: T4.3(G) U6.2(Q12)
NetU6_3: U6.3(Q13) U9.2(1A)
NetU10_3: U10.3(OUT) U12.1(I/O)

Not connected (* = marked no-connect by the designer): U6 1(Q11) 4(Q5) 5(Q4) 6(Q6) 7(Q3) 13(Q8) 14(Q7) 15(Q9); U9 1(NC)

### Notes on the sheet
- (near T3) PA5
- (near T3) PA0
- (near R26) PC13
- Oscillator frequency 30KHz
- STM32L152-EVAL  IDD_Measurement
- MB819
- 10
- 14

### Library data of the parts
C6 = Cap: Capacitor; Value: 10nF
C7 = CAP
C25 = Cap Pol1: as C34 on sheet MCU
JP4 = Jumper3
R17 R18 R26 R33 R35 R36 = res1: Resistor; Value: 1K
T3 T4 = STT5PF20V
U6 = M74HC4060TTR
U9 = 74LX1G04CTR
U10 = TSC101BILT
U12 = 74H1G66STR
